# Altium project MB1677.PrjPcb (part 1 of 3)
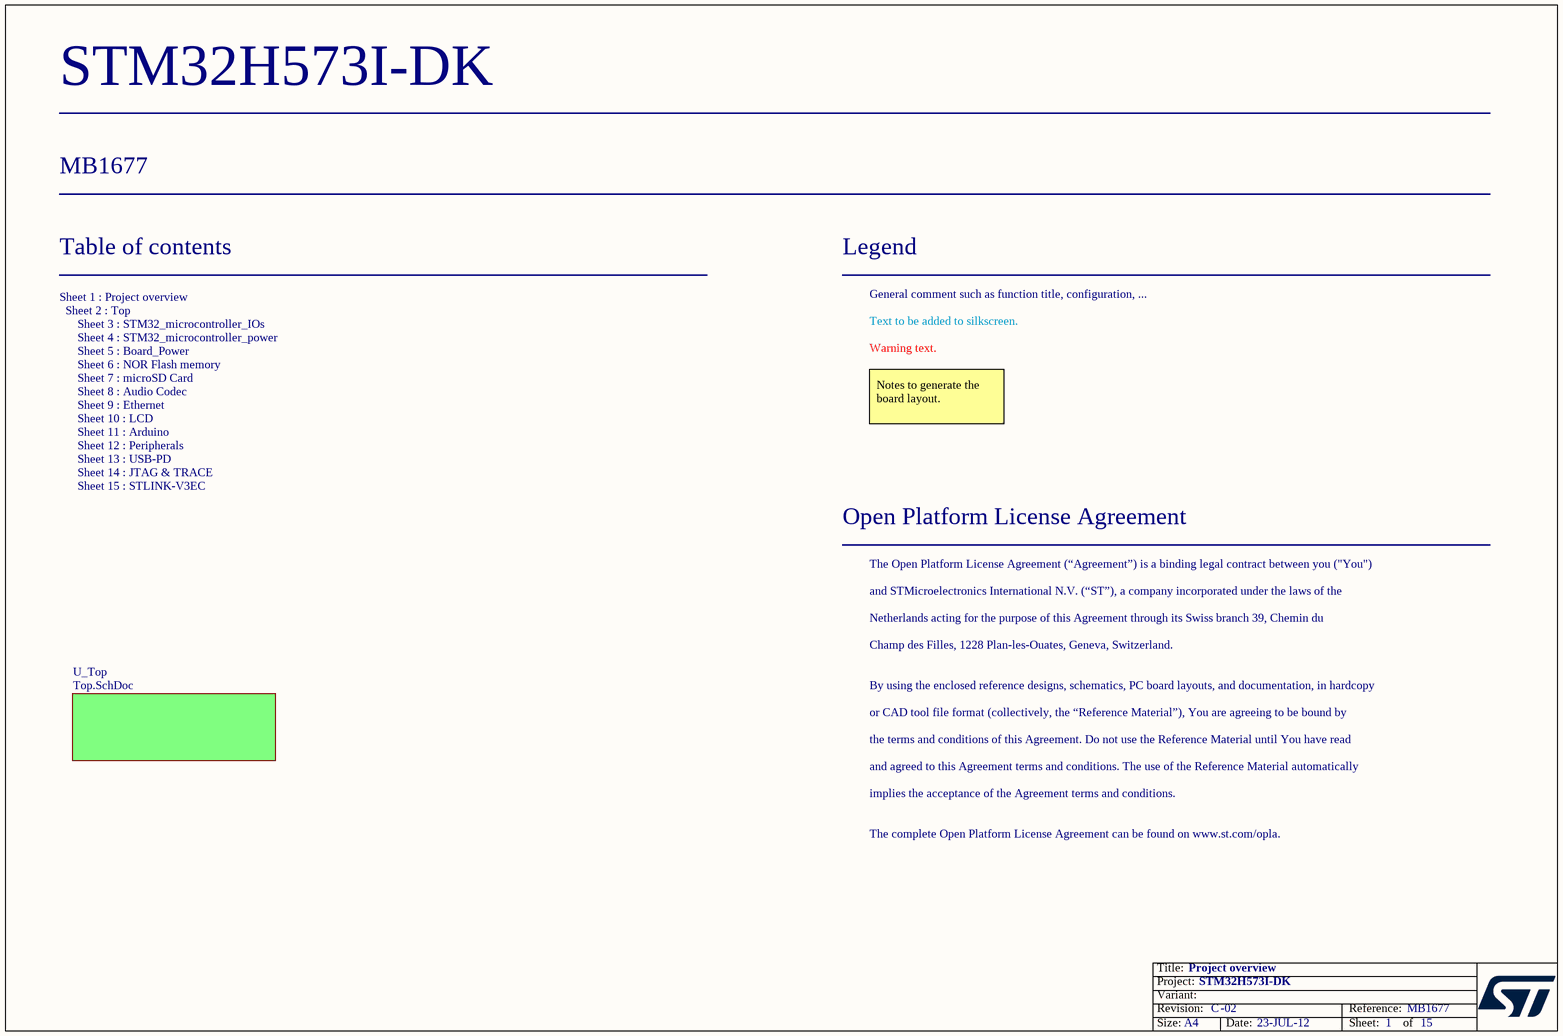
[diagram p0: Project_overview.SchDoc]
Board_Assembly_Revision: 02; Board_Document_Date: 23-JUL-12; Board_Name: STM32H573I-DK; Board_PCB_Revision: C; Board_Reference: MB1677
15 sheets, 390 parts. Net scope: flat (ports and power ports of the same name join across sheets).
Board file: MB1677.PcbDoc
Sheets:
  Project_overview.SchDoc
    U_Top = Top.SchDoc
      U_Audio_Codec = Audio_Codec.SchDoc
      U_LCD = LCD.SchDoc
      U_Peripherals = Peripherals.SchDoc
      U_Arduino = Arduino.SchDoc
      U_JTAG = JTAG.SchDoc
      U_Ethernet = Ethernet.SchDoc
      U_STLINK_V3EC = STLINK_V3EC.SchDoc
      U_Board_power = Board_power.SchDoc
      U_STM32_microcontroller_power = STM32_microcontroller_power.SchDoc
      U_STM32_microcontroller_IOs = STM32_microcontroller_IOs.SchDoc
      U_USB-PD = USB-PD.SchDoc
      U_microSDcard = microSDcard.SchDoc
      U_NOR Flash memory = NOR Flash memory.SchDoc

## Sheet Project_overview.SchDoc: Project overview
size A4; Date: Not used; ApprovedBy: Not used; CheckedBy: Not used; Author: Not used; CompanyName: STMicroelectronics; DrawnBy: Not used; Engineer: Not used; Organization: Not used; Address1: Not used; Address2: Not used; Address3: Not used; Address4: Not used; DocumentNumber: 1; Revision: Not used; SheetNumber: 1; SheetTotal: 15

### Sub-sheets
U_Top = Top.SchDoc: no entries

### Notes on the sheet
- Table of contents
- Legend
- General comment such as function title, configuration, ...
- Text to be added to silkscreen.
- Warning text.
- Notes to generate the board layout.
- Sheet 1 : Project overview
  Sheet 2 : Top
  Sheet 3 : STM32_microcontroller_IOs
  Sheet 4 : STM32_microcontroller_power
  Sheet 5 : Board_Power
  Sheet 6 : NOR Flash memory
  Sheet 7 : microSD Card
  Sheet 8 : Audio Codec
  Sheet 9 : Ethernet
  Sheet 10 : LCD
  Sheet 11 : Arduino
  Sheet 12 : Peripherals
  Sheet 13 : USB-PD
  Sheet 14 : JTAG & TRACE
  Sheet 15 : STLINK-V3EC
- Open Platform License Agreement
- The Open Platform License Agreement (“Agreement”) is a binding legal contract between you ("You")
- and STMicroelectronics International N.V. (“ST”), a company incorporated under the laws of the
- Netherlands acting for the purpose of this Agreement through its Swiss branch 39, Chemin du
- Champ des Filles, 1228 Plan-les-Ouates, Geneva, Switzerland.
- By using the enclosed reference designs, schematics, PC board layouts, and documentation, in hardcopy
- or CAD tool file format (collectively, the “Reference Material”), You are agreeing to be bound by
- the terms and conditions of this Agreement. Do not use the Reference Material until You have read
- and agreed to this Agreement terms and conditions. The use of the Reference Material automatically
- implies the acceptance of the Agreement terms and conditions.
- The complete Open Platform License Agreement can be found on www.st.com/opla.

## Sheet Top.SchDoc: TOP
size A3; Date: Not used; ApprovedBy: Not used; CheckedBy: Not used; Author: Not used; CompanyName: STMicroelectronics; DrawnBy: Not used; Engineer: Not used; Organization: Not used; Address1: Not used; Address2: Not used; Address3: Not used; Address4: Not used; DocumentNumber: 2; Revision: Not used; SheetNumber: 2; SheetTotal: 15
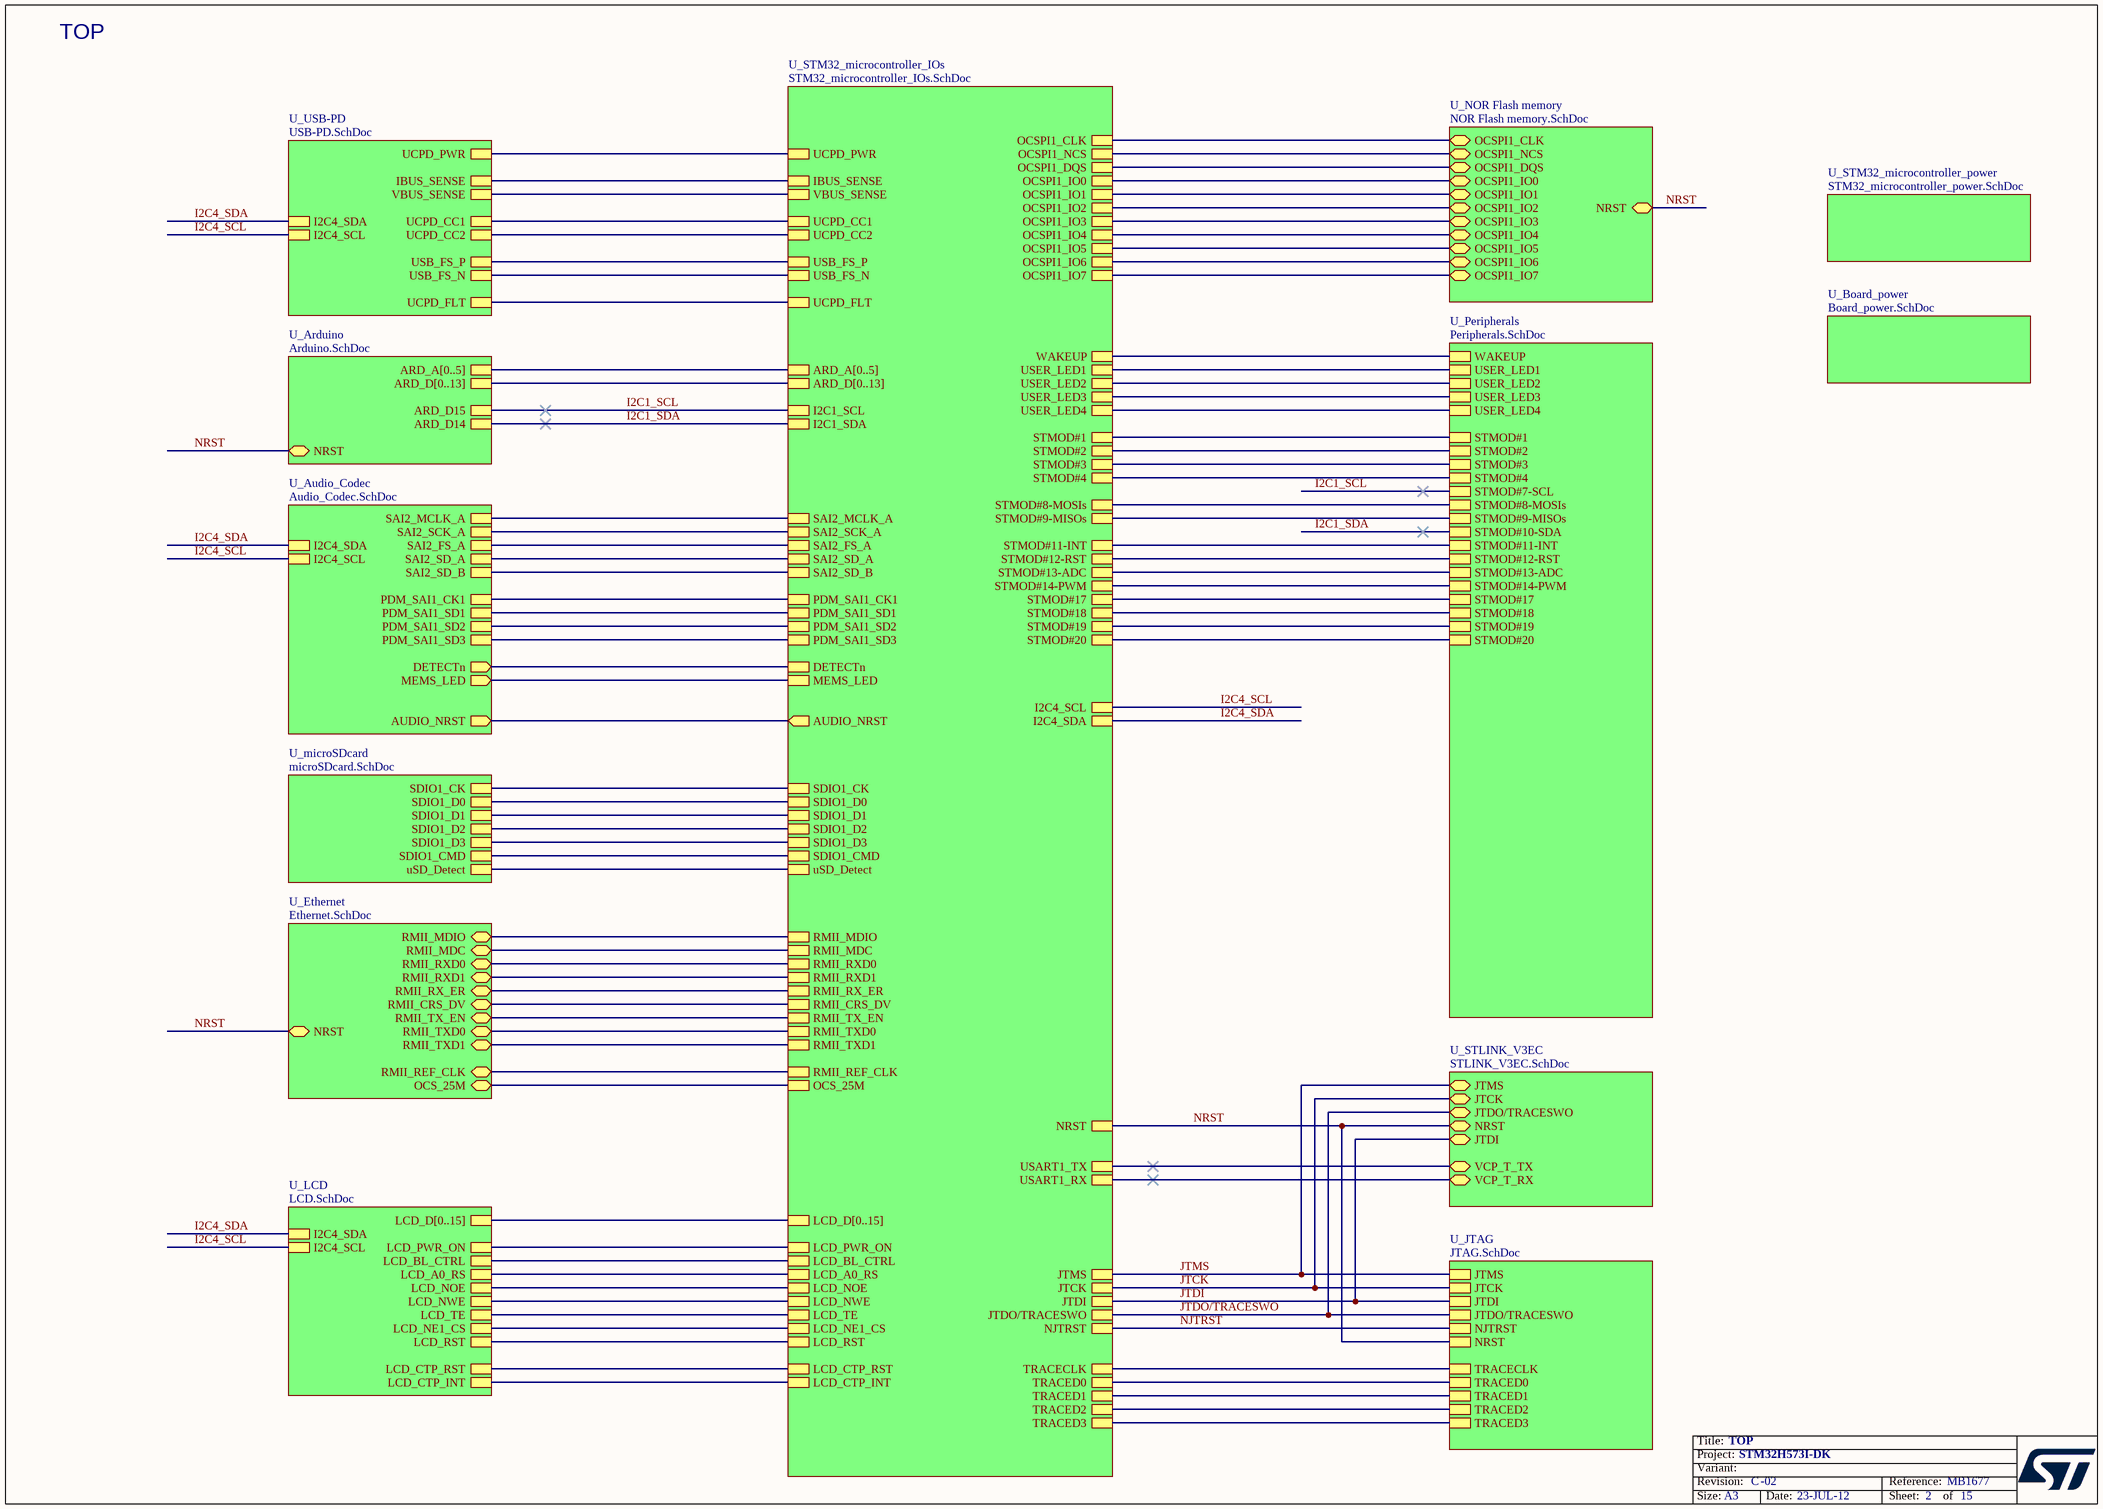
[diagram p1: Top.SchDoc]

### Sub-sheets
U_Arduino = Arduino.SchDoc: ARD_D15, ARD_D14, ARD_A[0..5], NRST (bidir), ARD_D[0..13]
U_Audio_Codec = Audio_Codec.SchDoc: AUDIO_NRST (out), MEMS_LED (out), SAI2_SCK_A, SAI2_MCLK_A, SAI2_SD_B, DETECTn (out), SAI2_FS_A, SAI2_SD_A, I2C4_SCL, I2C4_SDA, PDM_SAI1_CK1, PDM_SAI1_SD2, PDM_SAI1_SD1, PDM_SAI1_SD3
U_Board_power = Board_power.SchDoc: no entries
U_Ethernet = Ethernet.SchDoc: RMII_TXD0 (bidir), RMII_TX_EN (bidir), RMII_RXD0 (bidir), RMII_REF_CLK (bidir), RMII_CRS_DV (bidir), RMII_MDC (bidir), RMII_MDIO (bidir), NRST (bidir), RMII_TXD1 (bidir), RMII_RXD1 (bidir), RMII_RX_ER (bidir), OCS_25M (bidir)
U_JTAG = JTAG.SchDoc: JTMS, JTCK, JTDI, JTDO/TRACESWO, NJTRST, NRST, TRACED0, TRACED1, TRACECLK, TRACED2, TRACED3
U_LCD = LCD.SchDoc: LCD_BL_CTRL, LCD_PWR_ON, LCD_RST, LCD_A0_RS, LCD_CTP_RST, LCD_TE, LCD_NOE, LCD_NE1_CS, LCD_D[0..15], LCD_CTP_INT, LCD_NWE, I2C4_SCL, I2C4_SDA
U_microSDcard = microSDcard.SchDoc: SDIO1_D0, SDIO1_D1, SDIO1_D2, SDIO1_D3, SDIO1_CMD, SDIO1_CK, uSD_Detect
U_NOR Flash memory = NOR Flash memory.SchDoc: NRST (bidir), OCSPI1_IO0 (bidir), OCSPI1_IO1 (bidir), OCSPI1_IO2 (bidir), OCSPI1_IO3 (bidir), OCSPI1_IO4 (bidir), OCSPI1_IO5 (bidir), OCSPI1_IO6 (bidir), OCSPI1_IO7 (bidir), OCSPI1_DQS (bidir), OCSPI1_CLK (bidir), OCSPI1_NCS (bidir)
U_Peripherals = Peripherals.SchDoc: WAKEUP, USER_LED2, USER_LED1, STMOD#2, STMOD#1, STMOD#4, USER_LED3, USER_LED4, STMOD#14-PWM, STMOD#8-MOSIs, STMOD#3, STMOD#13-ADC, STMOD#9-MISOs, STMOD#7-SCL, STMOD#10-SDA, STMOD#11-INT, STMOD#12-RST, STMOD#17, STMOD#18, STMOD#19, STMOD#20
U_STLINK_V3EC = STLINK_V3EC.SchDoc: JTCK (bidir), JTMS (bidir), JTDI (bidir), VCP_T_TX (bidir), VCP_T_RX (bidir), JTDO/TRACESWO (bidir), NRST (bidir)
U_STM32_microcontroller_IOs = STM32_microcontroller_IOs.SchDoc: OCSPI1_NCS, SAI2_MCLK_A, NRST, OCSPI1_DQS, OCSPI1_CLK, LCD_D[0..15], uSD_Detect, RMII_MDIO, SAI2_SD_B, SAI2_FS_A, SAI2_SCK_A, SAI2_SD_A, USER_LED2, JTMS, JTCK, JTDI, JTDO/TRACESWO, NJTRST, OCSPI1_IO1, OCSPI1_IO2, OCSPI1_IO3, OCSPI1_IO4, OCSPI1_IO7, OCSPI1_IO6, OCSPI1_IO5, RMII_CRS_DV, WAKEUP, USER_LED1, RMII_RXD1, UCPD_CC1, STMOD#1, STMOD#2, STMOD#4, STMOD#3, STMOD#9-MISOs, STMOD#8-MOSIs, STMOD#13-ADC, USART1_TX, USART1_RX, STMOD#11-INT, STMOD#12-RST, STMOD#14-PWM, STMOD#18, RMII_REF_CLK, RMII_RXD0, RMII_TXD0, ARD_A[0..5], ARD_D[0..13], RMII_MDC, RMII_TXD1, RMII_TX_EN, SDIO1_D0, SDIO1_D1, SDIO1_D2, SDIO1_D3, SDIO1_CK, SDIO1_CMD, OCSPI1_IO0, LCD_RST, LCD_BL_CTRL, LCD_CTP_RST, LCD_PWR_ON, USER_LED3, USER_LED4, UCPD_CC2, OCS_25M, LCD_CTP_INT, LCD_NE1_CS, LCD_NOE, LCD_NWE, USB_FS_N, USB_FS_P, RMII_RX_ER, LCD_A0_RS, I2C4_SCL, I2C4_SDA, IBUS_SENSE, UCPD_PWR, UCPD_FLT, VBUS_SENSE, DETECTn, MEMS_LED, LCD_TE, I2C1_SCL, I2C1_SDA, AUDIO_NRST (out), PDM_SAI1_SD3, PDM_SAI1_CK1, PDM_SAI1_SD2, PDM_SAI1_SD1, STMOD#19, STMOD#20, STMOD#17, TRACECLK, TRACED0, TRACED1, TRACED2, TRACED3
U_STM32_microcontroller_power = STM32_microcontroller_power.SchDoc: no entries
U_USB-PD = USB-PD.SchDoc: UCPD_PWR, IBUS_SENSE, UCPD_CC1, UCPD_CC2, UCPD_FLT, USB_FS_P, USB_FS_N, VBUS_SENSE, I2C4_SCL, I2C4_SDA

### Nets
I2C1_SCL: sheet U_Peripherals/STMOD#7-SCL, sheet U_Arduino/ARD_D15, sheet U_STM32_microcontroller_IOs/I2C1_SCL
I2C1_SDA: sheet U_Peripherals/STMOD#10-SDA, sheet U_Arduino/ARD_D14, sheet U_STM32_microcontroller_IOs/I2C1_SDA
I2C4_SCL: sheet U_Audio_Codec/I2C4_SCL, sheet U_LCD/I2C4_SCL, sheet U_STM32_microcontroller_IOs/I2C4_SCL, sheet U_USB-PD/I2C4_SCL
I2C4_SDA: sheet U_Audio_Codec/I2C4_SDA, sheet U_LCD/I2C4_SDA, sheet U_STM32_microcontroller_IOs/I2C4_SDA, sheet U_USB-PD/I2C4_SDA
JTCK: sheet U_JTAG/JTCK, sheet U_STLINK_V3EC/JTCK, sheet U_STM32_microcontroller_IOs/JTCK
JTDI: sheet U_JTAG/JTDI, sheet U_STLINK_V3EC/JTDI, sheet U_STM32_microcontroller_IOs/JTDI
JTDO/TRACESWO: sheet U_JTAG/JTDO/TRACESWO, sheet U_STLINK_V3EC/JTDO/TRACESWO, sheet U_STM32_microcontroller_IOs/JTDO/TRACESWO
JTMS: sheet U_JTAG/JTMS, sheet U_STLINK_V3EC/JTMS, sheet U_STM32_microcontroller_IOs/JTMS
NJTRST: sheet U_JTAG/NJTRST, sheet U_STM32_microcontroller_IOs/NJTRST
NRST: sheet U_Arduino/NRST, sheet U_JTAG/NRST, sheet U_Ethernet/NRST, sheet U_STLINK_V3EC/NRST, sheet U_STM32_microcontroller_IOs/NRST, sheet U_NOR Flash memory/NRST
(unnamed): sheet U_Audio_Codec/AUDIO_NRST, sheet U_STM32_microcontroller_IOs/AUDIO_NRST
(unnamed): sheet U_Audio_Codec/MEMS_LED, sheet U_STM32_microcontroller_IOs/MEMS_LED  [a separate net that carries the same name]
(unnamed): sheet U_Audio_Codec/SAI2_SCK_A, sheet U_STM32_microcontroller_IOs/SAI2_SCK_A  [a separate net that carries the same name]
(unnamed): sheet U_Audio_Codec/SAI2_MCLK_A, sheet U_STM32_microcontroller_IOs/SAI2_MCLK_A  [a separate net that carries the same name]
(unnamed): sheet U_Audio_Codec/SAI2_SD_B, sheet U_STM32_microcontroller_IOs/SAI2_SD_B  [a separate net that carries the same name]
(unnamed): sheet U_Audio_Codec/DETECTn, sheet U_STM32_microcontroller_IOs/DETECTn  [a separate net that carries the same name]
(unnamed): sheet U_Audio_Codec/SAI2_FS_A, sheet U_STM32_microcontroller_IOs/SAI2_FS_A  [a separate net that carries the same name]
(unnamed): sheet U_Audio_Codec/SAI2_SD_A, sheet U_STM32_microcontroller_IOs/SAI2_SD_A  [a separate net that carries the same name]
(unnamed): sheet U_Audio_Codec/PDM_SAI1_CK1, sheet U_STM32_microcontroller_IOs/PDM_SAI1_CK1  [a separate net that carries the same name]
(unnamed): sheet U_Audio_Codec/PDM_SAI1_SD2, sheet U_STM32_microcontroller_IOs/PDM_SAI1_SD2  [a separate net that carries the same name]
(unnamed): sheet U_Audio_Codec/PDM_SAI1_SD1, sheet U_STM32_microcontroller_IOs/PDM_SAI1_SD1  [a separate net that carries the same name]
(unnamed): sheet U_Audio_Codec/PDM_SAI1_SD3, sheet U_STM32_microcontroller_IOs/PDM_SAI1_SD3  [a separate net that carries the same name]
(unnamed): sheet U_LCD/LCD_BL_CTRL, sheet U_STM32_microcontroller_IOs/LCD_BL_CTRL  [a separate net that carries the same name]
(unnamed): sheet U_LCD/LCD_PWR_ON, sheet U_STM32_microcontroller_IOs/LCD_PWR_ON  [a separate net that carries the same name]
(unnamed): sheet U_LCD/LCD_RST, sheet U_STM32_microcontroller_IOs/LCD_RST  [a separate net that carries the same name]
(unnamed): sheet U_LCD/LCD_A0_RS, sheet U_STM32_microcontroller_IOs/LCD_A0_RS  [a separate net that carries the same name]
(unnamed): sheet U_LCD/LCD_CTP_RST, sheet U_STM32_microcontroller_IOs/LCD_CTP_RST  [a separate net that carries the same name]
(unnamed): sheet U_LCD/LCD_TE, sheet U_STM32_microcontroller_IOs/LCD_TE  [a separate net that carries the same name]
(unnamed): sheet U_LCD/LCD_NOE, sheet U_STM32_microcontroller_IOs/LCD_NOE  [a separate net that carries the same name]
(unnamed): sheet U_LCD/LCD_NE1_CS, sheet U_STM32_microcontroller_IOs/LCD_NE1_CS  [a separate net that carries the same name]
(unnamed): sheet U_LCD/LCD_CTP_INT, sheet U_STM32_microcontroller_IOs/LCD_CTP_INT  [a separate net that carries the same name]
(unnamed): sheet U_LCD/LCD_NWE, sheet U_STM32_microcontroller_IOs/LCD_NWE  [a separate net that carries the same name]
(unnamed): sheet U_Peripherals/WAKEUP, sheet U_STM32_microcontroller_IOs/WAKEUP  [a separate net that carries the same name]
(unnamed): sheet U_Peripherals/USER_LED2, sheet U_STM32_microcontroller_IOs/USER_LED2  [a separate net that carries the same name]
(unnamed): sheet U_Peripherals/USER_LED1, sheet U_STM32_microcontroller_IOs/USER_LED1  [a separate net that carries the same name]
(unnamed): sheet U_Peripherals/STMOD#2, sheet U_STM32_microcontroller_IOs/STMOD#2  [a separate net that carries the same name]
(unnamed): sheet U_Peripherals/STMOD#1, sheet U_STM32_microcontroller_IOs/STMOD#1  [a separate net that carries the same name]
(unnamed): sheet U_Peripherals/STMOD#4, sheet U_STM32_microcontroller_IOs/STMOD#4  [a separate net that carries the same name]
(unnamed): sheet U_Peripherals/USER_LED3, sheet U_STM32_microcontroller_IOs/USER_LED3  [a separate net that carries the same name]
(unnamed): sheet U_Peripherals/USER_LED4, sheet U_STM32_microcontroller_IOs/USER_LED4  [a separate net that carries the same name]
(unnamed): sheet U_Peripherals/STMOD#14-PWM, sheet U_STM32_microcontroller_IOs/STMOD#14-PWM  [a separate net that carries the same name]
(unnamed): sheet U_Peripherals/STMOD#8-MOSIs, sheet U_STM32_microcontroller_IOs/STMOD#8-MOSIs  [a separate net that carries the same name]
(unnamed): sheet U_Peripherals/STMOD#3, sheet U_STM32_microcontroller_IOs/STMOD#3  [a separate net that carries the same name]
(unnamed): sheet U_Peripherals/STMOD#13-ADC, sheet U_STM32_microcontroller_IOs/STMOD#13-ADC  [a separate net that carries the same name]
(unnamed): sheet U_Peripherals/STMOD#9-MISOs, sheet U_STM32_microcontroller_IOs/STMOD#9-MISOs  [a separate net that carries the same name]
(unnamed): sheet U_Peripherals/STMOD#11-INT, sheet U_STM32_microcontroller_IOs/STMOD#11-INT  [a separate net that carries the same name]
(unnamed): sheet U_Peripherals/STMOD#12-RST, sheet U_STM32_microcontroller_IOs/STMOD#12-RST  [a separate net that carries the same name]
(unnamed): sheet U_Peripherals/STMOD#17, sheet U_STM32_microcontroller_IOs/STMOD#17  [a separate net that carries the same name]
(unnamed): sheet U_Peripherals/STMOD#18, sheet U_STM32_microcontroller_IOs/STMOD#18  [a separate net that carries the same name]
(unnamed): sheet U_Peripherals/STMOD#19, sheet U_STM32_microcontroller_IOs/STMOD#19  [a separate net that carries the same name]
(unnamed): sheet U_Peripherals/STMOD#20, sheet U_STM32_microcontroller_IOs/STMOD#20  [a separate net that carries the same name]
(unnamed): sheet U_JTAG/TRACED0, sheet U_STM32_microcontroller_IOs/TRACED0  [a separate net that carries the same name]
(unnamed): sheet U_JTAG/TRACED1, sheet U_STM32_microcontroller_IOs/TRACED1  [a separate net that carries the same name]
(unnamed): sheet U_JTAG/TRACECLK, sheet U_STM32_microcontroller_IOs/TRACECLK  [a separate net that carries the same name]
(unnamed): sheet U_JTAG/TRACED2, sheet U_STM32_microcontroller_IOs/TRACED2  [a separate net that carries the same name]
(unnamed): sheet U_JTAG/TRACED3, sheet U_STM32_microcontroller_IOs/TRACED3  [a separate net that carries the same name]
(unnamed): sheet U_Ethernet/RMII_TXD0, sheet U_STM32_microcontroller_IOs/RMII_TXD0  [a separate net that carries the same name]
(unnamed): sheet U_Ethernet/RMII_TX_EN, sheet U_STM32_microcontroller_IOs/RMII_TX_EN  [a separate net that carries the same name]
(unnamed): sheet U_Ethernet/RMII_RXD0, sheet U_STM32_microcontroller_IOs/RMII_RXD0  [a separate net that carries the same name]
(unnamed): sheet U_Ethernet/RMII_REF_CLK, sheet U_STM32_microcontroller_IOs/RMII_REF_CLK  [a separate net that carries the same name]
(unnamed): sheet U_Ethernet/RMII_CRS_DV, sheet U_STM32_microcontroller_IOs/RMII_CRS_DV  [a separate net that carries the same name]
(unnamed): sheet U_Ethernet/RMII_MDC, sheet U_STM32_microcontroller_IOs/RMII_MDC  [a separate net that carries the same name]
(unnamed): sheet U_Ethernet/RMII_MDIO, sheet U_STM32_microcontroller_IOs/RMII_MDIO  [a separate net that carries the same name]
(unnamed): sheet U_Ethernet/RMII_TXD1, sheet U_STM32_microcontroller_IOs/RMII_TXD1  [a separate net that carries the same name]
(unnamed): sheet U_Ethernet/RMII_RXD1, sheet U_STM32_microcontroller_IOs/RMII_RXD1  [a separate net that carries the same name]
(unnamed): sheet U_Ethernet/RMII_RX_ER, sheet U_STM32_microcontroller_IOs/RMII_RX_ER  [a separate net that carries the same name]
(unnamed): sheet U_Ethernet/OCS_25M, sheet U_STM32_microcontroller_IOs/OCS_25M  [a separate net that carries the same name]
(unnamed): sheet U_STLINK_V3EC/VCP_T_TX, sheet U_STM32_microcontroller_IOs/USART1_TX  [a separate net that carries the same name]
(unnamed): sheet U_STLINK_V3EC/VCP_T_RX, sheet U_STM32_microcontroller_IOs/USART1_RX  [a separate net that carries the same name]
(unnamed): sheet U_STM32_microcontroller_IOs/OCSPI1_NCS, sheet U_NOR Flash memory/OCSPI1_NCS  [a separate net that carries the same name]
(unnamed): sheet U_STM32_microcontroller_IOs/OCSPI1_DQS, sheet U_NOR Flash memory/OCSPI1_DQS  [a separate net that carries the same name]
(unnamed): sheet U_STM32_microcontroller_IOs/OCSPI1_CLK, sheet U_NOR Flash memory/OCSPI1_CLK  [a separate net that carries the same name]
(unnamed): sheet U_STM32_microcontroller_IOs/uSD_Detect, sheet U_microSDcard/uSD_Detect  [a separate net that carries the same name]
(unnamed): sheet U_STM32_microcontroller_IOs/OCSPI1_IO1, sheet U_NOR Flash memory/OCSPI1_IO1  [a separate net that carries the same name]
(unnamed): sheet U_STM32_microcontroller_IOs/OCSPI1_IO2, sheet U_NOR Flash memory/OCSPI1_IO2  [a separate net that carries the same name]
(unnamed): sheet U_STM32_microcontroller_IOs/OCSPI1_IO3, sheet U_NOR Flash memory/OCSPI1_IO3  [a separate net that carries the same name]
(unnamed): sheet U_STM32_microcontroller_IOs/OCSPI1_IO4, sheet U_NOR Flash memory/OCSPI1_IO4  [a separate net that carries the same name]
(unnamed): sheet U_STM32_microcontroller_IOs/OCSPI1_IO7, sheet U_NOR Flash memory/OCSPI1_IO7  [a separate net that carries the same name]
(unnamed): sheet U_STM32_microcontroller_IOs/OCSPI1_IO6, sheet U_NOR Flash memory/OCSPI1_IO6  [a separate net that carries the same name]
(unnamed): sheet U_STM32_microcontroller_IOs/OCSPI1_IO5, sheet U_NOR Flash memory/OCSPI1_IO5  [a separate net that carries the same name]
(unnamed): sheet U_STM32_microcontroller_IOs/UCPD_CC1, sheet U_USB-PD/UCPD_CC1  [a separate net that carries the same name]
(unnamed): sheet U_STM32_microcontroller_IOs/SDIO1_D0, sheet U_microSDcard/SDIO1_D0  [a separate net that carries the same name]
(unnamed): sheet U_STM32_microcontroller_IOs/SDIO1_D1, sheet U_microSDcard/SDIO1_D1  [a separate net that carries the same name]
(unnamed): sheet U_STM32_microcontroller_IOs/SDIO1_D2, sheet U_microSDcard/SDIO1_D2  [a separate net that carries the same name]
(unnamed): sheet U_STM32_microcontroller_IOs/SDIO1_D3, sheet U_microSDcard/SDIO1_D3  [a separate net that carries the same name]
(unnamed): sheet U_STM32_microcontroller_IOs/SDIO1_CK, sheet U_microSDcard/SDIO1_CK  [a separate net that carries the same name]
(unnamed): sheet U_STM32_microcontroller_IOs/SDIO1_CMD, sheet U_microSDcard/SDIO1_CMD  [a separate net that carries the same name]
(unnamed): sheet U_STM32_microcontroller_IOs/OCSPI1_IO0, sheet U_NOR Flash memory/OCSPI1_IO0  [a separate net that carries the same name]
(unnamed): sheet U_STM32_microcontroller_IOs/UCPD_CC2, sheet U_USB-PD/UCPD_CC2  [a separate net that carries the same name]
(unnamed): sheet U_STM32_microcontroller_IOs/USB_FS_N, sheet U_USB-PD/USB_FS_N  [a separate net that carries the same name]
(unnamed): sheet U_STM32_microcontroller_IOs/USB_FS_P, sheet U_USB-PD/USB_FS_P  [a separate net that carries the same name]
(unnamed): sheet U_STM32_microcontroller_IOs/IBUS_SENSE, sheet U_USB-PD/IBUS_SENSE  [a separate net that carries the same name]
(unnamed): sheet U_STM32_microcontroller_IOs/UCPD_PWR, sheet U_USB-PD/UCPD_PWR  [a separate net that carries the same name]
(unnamed): sheet U_STM32_microcontroller_IOs/UCPD_FLT, sheet U_USB-PD/UCPD_FLT  [a separate net that carries the same name]
(unnamed): sheet U_STM32_microcontroller_IOs/VBUS_SENSE, sheet U_USB-PD/VBUS_SENSE  [a separate net that carries the same name]

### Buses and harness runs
bus sheet U_Arduino/ARD_A[0..5] = sheet U_STM32_microcontroller_IOs/ARD_A[0..5]
bus sheet U_Arduino/ARD_D[0..13] = sheet U_STM32_microcontroller_IOs/ARD_D[0..13]
bus sheet U_LCD/LCD_D[0..15] = sheet U_STM32_microcontroller_IOs/LCD_D[0..15]

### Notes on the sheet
- TOP

## Sheet Audio_Codec.SchDoc: Audio Codec
size A4; Date: Not used; ApprovedBy: Not used; CheckedBy: Not used; Author: Not used; CompanyName: STMicroelectronics; DrawnBy: Not used; Engineer: Not used; Organization: Not used; Address1: Not used; Address2: Not used; Address3: Not used; Address4: Not used; DocumentNumber: 8; Revision: Not used; SheetNumber: 8; SheetTotal: 15
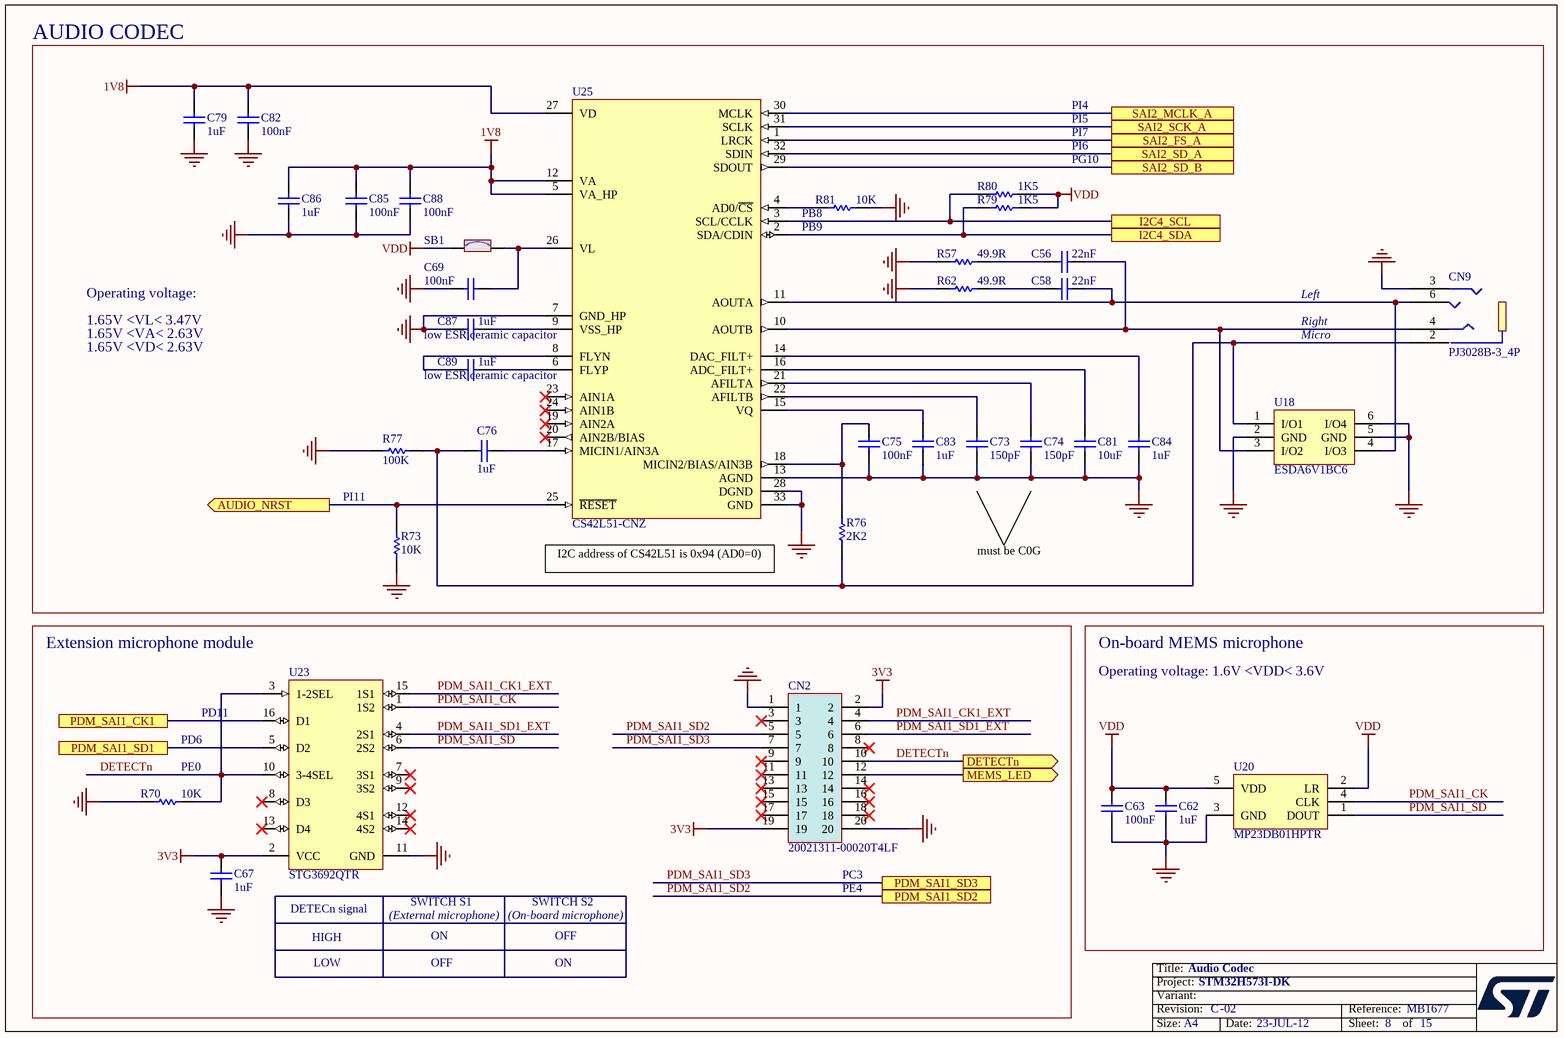
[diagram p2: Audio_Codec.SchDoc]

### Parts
C56  value 22nF  [C0603]  (hidden comment: Capacitor)
C58  value 22nF  [C0603]  (hidden comment: Capacitor)
C62  value 1uF  [C0402]  (hidden comment: Capacitor)
C63  value 100nF  [C0402]  (hidden comment: Capacitor)
C67  value 1uF  [C0402]  (hidden comment: Capacitor)
C69  value 100nF  [C0402]  (hidden comment: Capacitor)
C73  value 150pF  [C0402]  (hidden comment: Capacitor)
C74  value 150pF  [C0402]  (hidden comment: Capacitor)
C75  value 100nF  [C0402]  (hidden comment: Capacitor)
C76  value 1uF  [C0402]  (hidden comment: Capacitor)
C79  value 1uF  [C0402]  (hidden comment: Capacitor)
C81  value 10uF  [C0603]  (hidden comment: Capacitor)
C82  value 100nF  [C0402]  (hidden comment: Capacitor)
C83  value 1uF  [C0402]  (hidden comment: Capacitor)
C84  value 1uF  [C0402]  (hidden comment: Capacitor)
C85  value 100nF  [C0402]  (hidden comment: Capacitor)
C86  value 1uF  [C0402]  (hidden comment: Capacitor)
C87  value 1uF  [C0402]  (hidden comment: Capacitor)
C88  value 100nF  [C0402]  (hidden comment: Capacitor)
C89  value 1uF  [C0402]  (hidden comment: Capacitor)
CN2  value 20021311-00020T4LF  [CON_FCI_20021311-XXX20XXLF]  (hidden comment: Socket 10x2)
CN9  value PJ3028B-3_4P  [CON_PHONE-JACK-3P5_HY_PJ3028B]  (hidden comment: Jack_PJ3028B-3_4P)
R57  value 49.9R  [R0603]  (hidden comment: Resistor)
R62  value 49.9R  [R0603]  (hidden comment: Resistor)
R70  value 10K  [R0402]  (hidden comment: Resistor)
R73  value 10K  [R0402]  (hidden comment: Resistor)
R76  value 2K2  [R0402]  (hidden comment: Resistor)
R77  value 100K  [R0402]  (hidden comment: Resistor)
R79  value 1K5  [R0402]  (hidden comment: Resistor)
R80  value 1K5  [R0402]  (hidden comment: Resistor)
R81  value 10K  [R0402]  (hidden comment: Resistor)
SB1  SB_ON  [SOLDER-BRIDGE_R0603-0R]  (value not drawn)
U18  ESDA6V1BC6  [ESD_SOT23-6L]
U20  value MP23DB01HPTR  [MIC_STM_MP23DB01MMTR]  (hidden comment: MP23DB01MMTR)
U23  STG3692QTR  [ICC_UFQFN16-EPAD_2P6X1P8_P040]
U25  CS42L51-CNZ  [ICC_QFN32-EPAD_5X5_P050]

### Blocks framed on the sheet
AUDIO CODEC: C56 C58 C69 C73-C76 C79 C81-C89 CN9 R57 R62 R73 R76 R77 R79-R81 SB1 U18 U25
Extension microphone module: C67 CN2 R70 U23
On-board MEMS microphone: C62 C63 U20

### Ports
AUDIO_NRST (out), DETECTn (out), I2C4_SCL, I2C4_SDA, MEMS_LED (out), PDM_SAI1_CK1, PDM_SAI1_SD1, PDM_SAI1_SD2, PDM_SAI1_SD3, SAI2_FS_A, SAI2_MCLK_A, SAI2_SCK_A, SAI2_SD_A, SAI2_SD_B

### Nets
1V8: C79.2 C82.2 C85.2 C86.2 C88.2 U25.5(VA_HP) U25.12(VA) U25.27(VD)
3V3: C67.2 CN2.2 CN2.19 U23.2(VCC)
GND: C62.2 C63.1 C67.1 C69.2 C73.1 C74.1 C75.2 C79.1 C81.1 C82.1 C83.1 C84.1 C85.1 C86.1 C87.1 C88.1 CN2.1 CN2.20 CN9.3 R57.2 R62.2 R70.1 R73.2 R77.2 R81.2 U18.2(GND) U18.5(GND) U18.6(I/O4) U20.3(GND) U23.11(GND) U25.7(GND_HP) U25.13(AGND) U25.28(DGND) U25.33(GND)
VDD: C62.1 C63.2 R79.2 R80.2 SB1.1 U20.2(LR) U20.5(VDD)
AUDIO_NRST: R73.1 U25.25(~{RESET}) ; port AUDIO_NRST
DETECTn: CN2.10 R70.2 U23.3(1-2SEL) U23.10(3-4SEL) ; port DETECTn
I2C4_SCL: R80.1 U25.3(SCL/CCLK) ; port I2C4_SCL
I2C4_SDA: R79.1 U25.2(SDA/CDIN) ; port I2C4_SDA
MEMS_LED: CN2.12 ; port MEMS_LED
PDM_SAI1_CK: U20.4(CLK) U23.1(1S2)
PDM_SAI1_CK1: U23.16(D1) ; port PDM_SAI1_CK1
PDM_SAI1_CK1_EXT: CN2.4 U23.15(1S1)
PDM_SAI1_SD: U20.1(DOUT) U23.6(2S2)
PDM_SAI1_SD1: U23.5(D2) ; port PDM_SAI1_SD1
PDM_SAI1_SD1_EXT: CN2.6 U23.4(2S1)
PDM_SAI1_SD2: CN2.5 ; port PDM_SAI1_SD2
PDM_SAI1_SD3: CN2.7 ; port PDM_SAI1_SD3
SAI2_FS_A: U25.1(LRCK) ; port SAI2_FS_A
SAI2_MCLK_A: U25.30(MCLK) ; port SAI2_MCLK_A
SAI2_SCK_A: U25.31(SCLK) ; port SAI2_SCK_A
SAI2_SD_A: U25.32(SDIN) ; port SAI2_SD_A
SAI2_SD_B: U25.29(SDOUT) ; port SAI2_SD_B
NetC56_1: C56.1 R57.1
NetC56_2: C56.2 CN9.4 U18.3(I/O2) U25.10(AOUTB)
NetC58_1: C58.1 R62.1
NetC58_2: C58.2 CN9.6 U18.4(I/O3) U25.11(AOUTA)
NetC69_1: C69.1 SB1.2 U25.26(VL)
NetC73_2: C73.2 U25.22(AFILTB)
NetC74_2: C74.2 U25.21(AFILTA)
NetC75_1: C75.1 R76.2 U25.18(MICIN2/BIAS/AIN3B)
NetC76_1: C76.1 CN9.2 R76.1 R77.1 U18.1(I/O1)
NetC76_2: C76.2 U25.17(MICIN1/AIN3A)
NetC81_2: C81.2 U25.16(ADC_FILT+)
NetC83_2: C83.2 U25.15(VQ)
NetC84_2: C84.2 U25.14(DAC_FILT+)
NetC87_2: C87.2 U25.9(VSS_HP)
NetC89_1: C89.1 U25.8(FLYN)
NetC89_2: C89.2 U25.6(FLYP)
NetR81_1: R81.1 U25.4(AD0/~{CS})

Not connected (* = marked no-connect by the designer): CN2 3* 8* 9* 11* 13* 14* 15* 16* 17* 18*; U23 7(3S1)* 8(D3)* 9(3S2)* 12(4S1)* 13(D4)* 14(4S2)*; U25 19(AIN2A)* 20(AIN2B/BIAS)* 23(AIN1A)* 24(AIN1B)*

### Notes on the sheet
- PI4
- PI5
- PI7
- PI6
- PG10
- (near R81) PB8
- (near R81) PB9
- Operating voltage:
- Left
- 1.65V <VL< 3.47V
- 1.65V <VA< 2.63V
- 1.65V <VD< 2.63V
- low ESR ceramic capacitor
- Right
- Micro
- PI11
- (near U25) I2C address of CS42L51 is 0x94 (AD0=0)
- must be C0G
- PD11
- Operating voltage: 1.6V <VDD< 3.6V
- PD6
- (near R70) PE0
- DETECn signal
- (External microphone)
- (near U23) SWITCH S1
- (On-board microphone)
- SWITCH S2
- PE4
- (near CN2) PC3
- HIGH
- LOW
- OFF
- ON

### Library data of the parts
C56 C58 = MCD-00555: Capacitor, MLCC, 22nF, 10%, 25V, X7R, 0603, T=0,8mm; Manufacturer_Part_Number: CC0603KRX7R8BB223; Manufacturer: YAGEO; Provided_By: SUBCO
C62 C79 C83 C84 C86 C87 C89 = MCD-01722: Capacitor, 1uF, 10V, X5R, 10%, 0402, T=0.5mm; Manufacturer_Part_Number: CC0402KRX5R6BB105; Manufacturer: YAGEO; Provided_By: SUBCO
C63 = MCD-00102: Capacitor, MLCC, 100nF, 16V, X7R, +/-10%, 0402, T=0,5mm; Part_Preference: Not recommended; Manufacturer: YAGEO; Manufacturer_Part_Number: CC0402KRX7R7BB104; Alternate_Manufacturer: MURATA; Alternate_Manufacturer_Part_Number: GCM155R71C104KA55D; Order_Code_RS: 616-9701
C67 C76 = MCD-00095: Capacitor, MLCC, 1uF, 25V, X5R, +/-10%, 0402, T=0,5mm; Part_Preference: Recommended; Manufacturer: MURATA; Manufacturer_Part_Number: GRM155R61E105KA12; Alternate_Manufacturer_Part_Number: GRM155R60J105KE19; Order_Code_RS: 846-7287
C69 C75 C82 C85 C88 = MCD-00102: Capacitor, MLCC, 100nF, 16V, X7R, 10%, 0402, T=0,5mm; Manufacturer_Part_Number: CC0402KRX7R7BB104; Manufacturer: YAGEO; Alternate_Manufacturer_Part_Number: GCM155R71C104KA55D; Alternate_Manufacturer: MURATA; Provided_By: SUBCO
C73 C74 = MCD-00672: Capacitor, MLCC, 150pF, 50V, NPO, 5%, 0402, T=0,5mm; Manufacturer_Part_Number: CC0402JRNPO9BN151; Manufacturer: YAGEO; Provided_By: SUBCO
C81 = MCD-00098: Capacitor, MLCC, 10uF, 6V3, X5R, 10%, 0603, T=0,8mm; Manufacturer_Part_Number: CC0603KRX5R5BB106; Manufacturer: YAGEO; Provided_By: SUBCO
CN2 = MCD-00147: Socket for MB1299, 10x2, 1.27mm, VR, TH, Height 4.30mm/2.40mm; Part_Preference: Recommended; Part_Type: Connector; Manufacturer: AMPHENOL ICC (FCI); Alternate_Manufacturer: JIUBABA; Alternate_Manufacturer_Part_Number: 234220S1410
CN9 = MCD-00263: Connector Jack Socket Stereo 3.5mm, 4 pins, RA, SMT, Black; Part_Preference: Recommended; Manufacturer: QIAOD
R57 R62 = MCD-00564: Resistor,49R9,0603,1%,1/10W; Manufacturer_Part_Number: RC0603FR-0749R9L; Manufacturer: YAGEO; Provided_By: SUBCO
R70 = MCD-00053: Resistor,10K,0402,1%,1/16W; BMS_Part_Number: 9131590; Part_Preference: Recommended; Manufacturer: YAGEO; Manufacturer_Part_Number: RC0402FR-0710KL
R73 R81 = MCD-00053: Resistor,10K,0402,1%,1/16W; Manufacturer_Part_Number: RC0402FR-0710KL; Manufacturer: YAGEO; Provided_By: SUBCO
R76 = MCD-00057: Resistor,2K2,0402,1%,1/16W; Part_Preference: Recommended; Manufacturer: YAGEO; Manufacturer_Part_Number: RC0402FR-072K2L
R77 = MCD-00059: Resistor,100K,0402,1%,1/16W; Manufacturer_Part_Number: RC0402FR-07100KL; Manufacturer: YAGEO; Alternate_Manufacturer_Part_Number: RT0402FRE07100KL; Provided_By: SUBCO
R79 R80 = MCD-00068: Resistor,1K5,0402,1%,1/16W; Manufacturer_Part_Number: RC0402FR-071K5L; Manufacturer: YAGEO; Provided_By: SUBCO
SB1 = MCD-00071: Solder Bridge ON; Part_Type: Mechanical; Manufacturer_Part_Number: RC0603JR-070RL; Manufacturer: YAGEO; Provided_By: SUBCO
U18 = MCD-00247: Quad Bidir ESD protection; BMS_Part_Number: 9179038; Part_Preference: Recommended; Part_Type: Diode; Manufacturer: STMICROELECTRONICS; Manufacturer_HQ_COO: EU
U20 = MCD-02122: MEMS sensors , omnidirectionnal digital microphone; Part_Type: IC; Part_Preference: Recommended; Manufacturer: STMICROELECTRONICS; Manufacturer_HQ_COO: EU; Component_Country_Of_Origin: China; ShowFields: YES; ID: 4222
U23 = MCD-00317: Low voltage high bandwidth quad SPDT switch; BMS_Part_Number: 9159018; Part_Preference: Recommended; Part_Type: IC; Manufacturer: STMICROELECTRONICS
U25 = MCD-00265: Low-Power, Stereo Codec with Headphone Amp; Part_Type: IC; Manufacturer: CIRRUS LOGIC; Provided_By: SUBCO

## Sheet LCD.SchDoc: LCD
size A4; Date: Not used; ApprovedBy: Not used; CheckedBy: Not used; Author: Not used; CompanyName: STMicroelectronics; DrawnBy: Not used; Engineer: Not used; Organization: Not used; Address1: Not used; Address2: Not used; Address3: Not used; Address4: Not used; DocumentNumber: 10; Revision: Not used; SheetNumber: 10; SheetTotal: 15
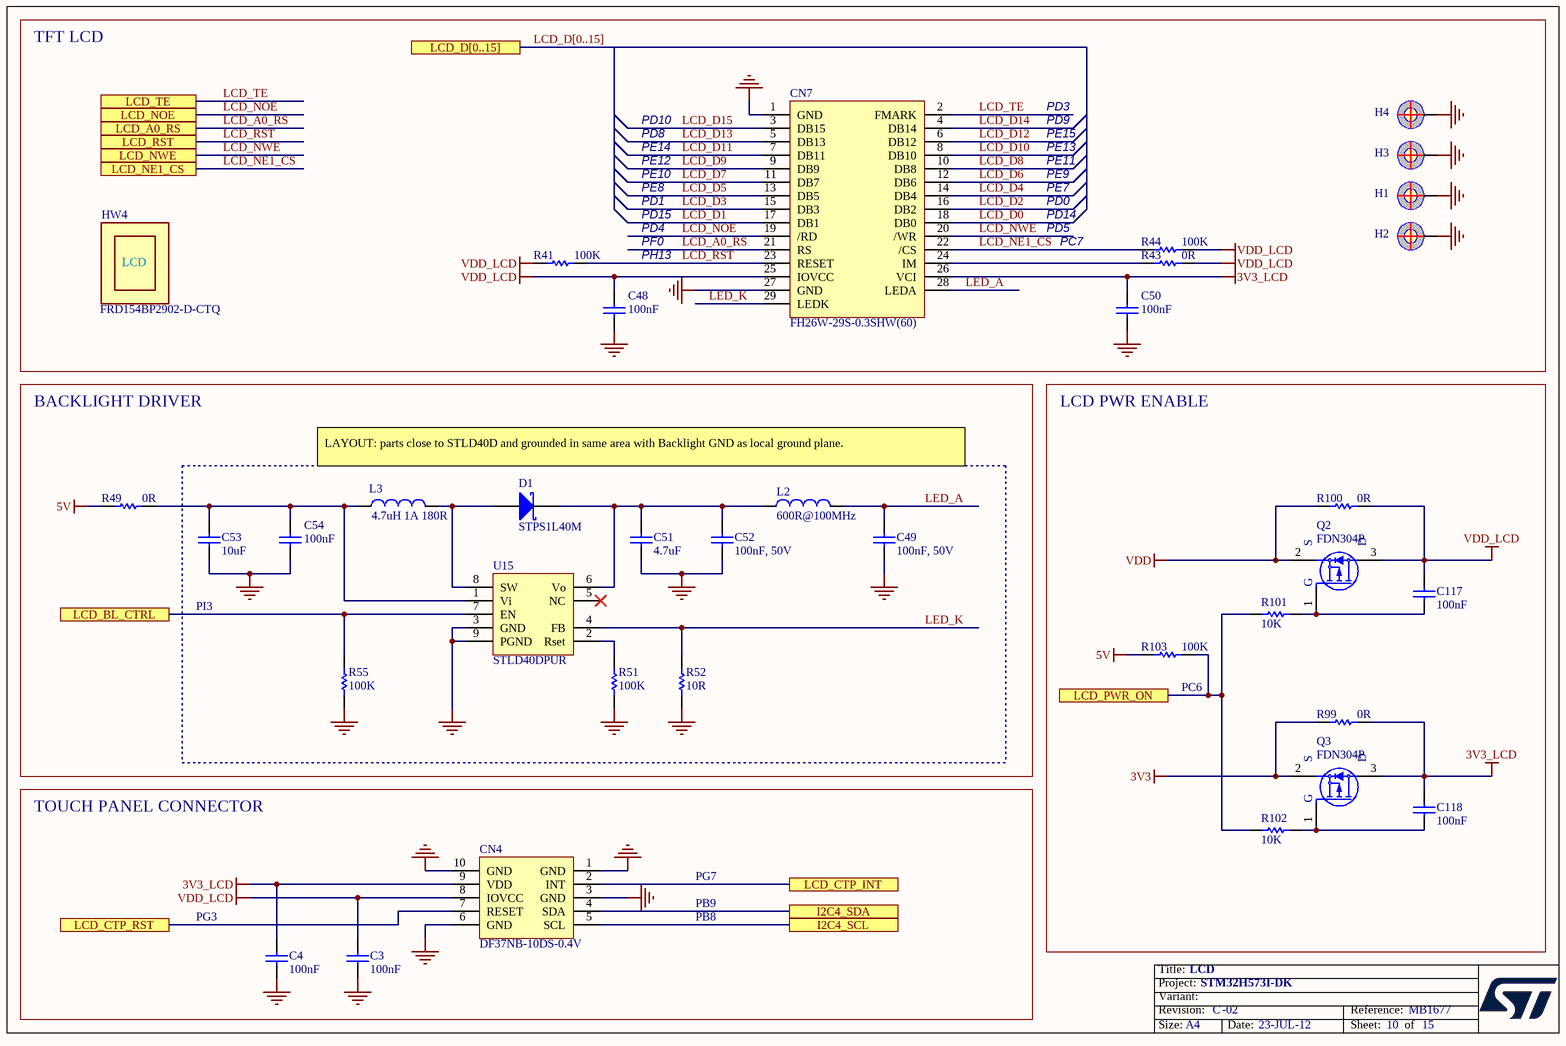
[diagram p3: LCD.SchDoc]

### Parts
C3  value 100nF  [C0402]  (hidden comment: Capacitor)
C4  value 100nF  [C0402]  (hidden comment: Capacitor)
C48  value 100nF  [C0402]  (hidden comment: Capacitor)
C49  value 100nF, 50V  [C0603]  (hidden comment: Capacitor)
C50  value 100nF  [C0402]  (hidden comment: Capacitor)
C51  value 4.7uF  [C1206_H1P25]  (hidden comment: Capacitor)
C52  value 100nF, 50V  [C0603]  (hidden comment: Capacitor)
C53  value 10uF  [C0603]  (hidden comment: Capacitor)
C54  value 100nF  [C0402]  (hidden comment: Capacitor)
C117  value 100nF  [C0402]  (hidden comment: Capacitor)
C118  value 100nF  [C0402]  (hidden comment: Capacitor)
CN4  DF37NB-10DS-0.4V  [CON_HRS_DF37NB-10DS-04V]
CN7  value FH26W-29S-0.3SHW(60)  [CON_HRS_FH26-29S-03SHW]  (hidden comment: FH26-29S-0.3SHW)
D1  STPS1L40M  [DIO_DO216-AA]
H1  POSITION HOLE  [PTH_M1261-3005-N_3P5X6_M3_H14]  (value not drawn)  (no BOM)
H2  POSITION HOLE  [PTH_M1261-3005-N_3P5X6_M3_H14]  (value not drawn)  (no BOM)
H3  POSITION HOLE  [PTH_M1261-3005-N_3P5X6_M3_H14]  (value not drawn)  (no BOM)
H4  POSITION HOLE  [PTH_M1261-3005-N_3P5X6_M3_H14]  (value not drawn)  (no BOM)
HW4  value FRD154BP2902-D-CTQ  [LCD_DRAWING_FRIDA_FRD154BP2902-D-CTQ]  (hidden comment: LCD_MODULE)  (mechanical)
L2  value 600R@100MHz  [L0603]  (hidden comment: BEAD)
L3  value 4.7uH 1A 180R  [L1210_LQH]  (hidden comment: Inductor)
Q2  value FDN304P  [MOS_SOT23]  (hidden comment: MOSFET_FDN304P)
Q3  value FDN304P  [MOS_SOT23]  (hidden comment: MOSFET_FDN304P)
R41  value 100K  [R0402]  (hidden comment: Resistor)
R43  value 0R  [R0402]  (hidden comment: Resistor)
R44  value 100K  [R0402]  (hidden comment: Resistor)
R49  value 0R  [R0402]  (hidden comment: Resistor)
R51  value 100K  [R0402]  (hidden comment: Resistor)
R52  value 10R  [R0402]  (hidden comment: Resistor)
R55  value 100K  [R0402]  (hidden comment: Resistor)
R99  value 0R  [R0402]  (hidden comment: Resistor)
R100  value 0R  [R0402]  (hidden comment: Resistor)
R101  value 10K  [R0402]  (hidden comment: Resistor)
R102  value 10K  [R0402]  (hidden comment: Resistor)
R103  value 100K  [R0402]  (hidden comment: Resistor)
U15  STLD40DPUR  [ICC_QFN8-EPAD_3X3_P065]

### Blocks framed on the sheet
TFT LCD: C48 C50 CN7 H1-H4 HW4 R41 R43 R44
BACKLIGHT DRIVER: R49
LCD PWR ENABLE: C117 C118 Q2 Q3 R99-R103
PI3: C49 C51-C54 D1 L2 L3 R51 R52 R55 U15
TOUCH PANEL CONNECTOR: C3 C4 CN4

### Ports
I2C4_SCL, I2C4_SDA, LCD_A0_RS, LCD_BL_CTRL, LCD_CTP_INT, LCD_CTP_RST, LCD_D[0..15], LCD_NE1_CS, LCD_NOE, LCD_NWE, LCD_PWR_ON, LCD_RST, LCD_TE

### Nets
3V3: Q3.2(S) R99.1
3V3_LCD: C4.2 C50.1 C118.2 CN4.9(VDD) CN7.26(VCI) Q3.3(D) R99.2
5V: R49.1 R103.1
GND: C3.1 C4.1 C48.2 C49.1 C50.2 C51.1 C52.1 C53.1 C54.2 CN4.1(GND) CN4.3(GND) CN4.6(GND) CN4.10(GND) CN7.1(GND) CN7.27(GND) H1.1 H2.1 H3.1 H4.1 R51.1 R52.1 R55.1 U15.3(GND) U15.9(PGND)
VDD: Q2.2(S) R100.1
VDD_LCD: C3.2 C48.1 C117.2 CN4.8(IOVCC) CN7.25(IOVCC) Q2.3(D) R41.1 R43.2 R44.2 R100.2
I2C4_SCL: CN4.5(SCL) ; port I2C4_SCL
I2C4_SDA: CN4.4(SDA) ; port I2C4_SDA
LCD_A0_RS: CN7.21(RS) ; port LCD_A0_RS
LCD_BL_CTRL: R55.2 U15.7(EN) ; port LCD_BL_CTRL
LCD_CTP_INT: CN4.2(INT) ; port LCD_CTP_INT
LCD_CTP_RST: CN4.7(RESET) ; port LCD_CTP_RST
LCD_D0: CN7.18(DB0)
LCD_D1: CN7.17(DB1)
LCD_D2: CN7.16(DB2)
LCD_D3: CN7.15(DB3)
LCD_D4: CN7.14(DB4)
LCD_D5: CN7.13(DB5)
LCD_D6: CN7.12(DB6)
LCD_D7: CN7.11(DB7)
LCD_D8: CN7.10(DB8)
LCD_D9: CN7.9(DB9)
LCD_D10: CN7.8(DB10)
LCD_D11: CN7.7(DB11)
LCD_D12: CN7.6(DB12)
LCD_D13: CN7.5(DB13)
LCD_D14: CN7.4(DB14)
LCD_D15: CN7.3(DB15)
LCD_NE1_CS: CN7.22(/CS) R44.1 ; port LCD_NE1_CS
LCD_NOE: CN7.19(/RD) ; port LCD_NOE
LCD_NWE: CN7.20(/WR) ; port LCD_NWE
LCD_PWR_ON: R101.1 R102.1 R103.2 ; port LCD_PWR_ON
LCD_RST: CN7.23(RESET) R41.2 ; port LCD_RST
LCD_TE: CN7.2(FMARK) ; port LCD_TE
LED_A: C49.2 CN7.28(LEDA) L2.2
LED_K: CN7.29(LEDK) R52.2 U15.4(FB)
NetC51_2: C51.2 C52.2 D1.2(K) L2.1 U15.6(Vo)
NetC53_2: C53.2 C54.1 L3.1 R49.2 U15.1(Vi)
NetC117_1: C117.1 Q2.1(G) R101.2
NetC118_1: C118.1 Q3.1(G) R102.2
NetCN7_24: CN7.24(IM) R43.1
NetD1_1: D1.1(A) L3.2 U15.8(SW)
NetR51_2: R51.2 U15.2(Rset)

Not connected (* = marked no-connect by the designer): U15 5(NC)*

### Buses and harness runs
bus LCD_D[0..15] = port LCD_D[0..15]

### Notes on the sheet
- PD3
- PD10
- PD8
- PE14
- PE12
- PE10
- PD9
- PE15
- PE13
- PE11
- PE9
- PE8
- PD1
- PD15
- PD4
- PF0
- PE7
- PD0
- PD14
- PD5
- PC7
- PH13
- LAYOUT: parts close to STLD40D and grounded in same area with Backlight GND as local ground plane.
- (near R103) PC6
- PG3
- PB9
- PB8
- PG7

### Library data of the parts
C3 C4 C117 C118 = MCD-00006: Capacitor, MLCC, 100nF, 16V, X7R, 10%, 0402, T=0.5mm; Manufacturer_Part_Number: CC0402KRX7R7BB104; Manufacturer: YAGEO; Alternate_Manufacturer_Part_Number: GCM155R71C104KA55D; Alternate_Manufacturer: MURATA; ECCN_US: EAR99; ECCN_EU: NEC; Provided_By: SUBCO
C48 C50 C54 = MCD-00006: Capacitor, MLCC, 100nF, 16V, X7R, 10%, 0402, T=0.5mm; Manufacturer_Part_Number: CC0402KRX7R7BB104; Manufacturer: YAGEO; Alternate_Manufacturer_Part_Number: GCM155R71C104KA55D; Alternate_Manufacturer: MURATA; Provided_By: SUBCO
C49 C52 = MCD-01099: Capacitor,100nF,50V,X7R,10%,0603; Manufacturer_Part_Number: CC0603KRX7R9BB104; Manufacturer: YAGEO; BMS_Part_Number: 9142278; Provided_By: SUBCO
C51 = MCD-00013: Capacitor, MLCC, 4.7uF, 50V, X7R, 10%, 1206, T=1,27mm; Manufacturer_Part_Number: 12065C475KAT2A; Manufacturer: AVX; ECCN_US: EAR99; ECCN_EU: NEC; Provided_By: SUBCO
C53 = MCD-00099: Capacitor, MLCC, 10uF, 10V, X5R, 10%, 0603, T=0,8mm; Manufacturer_Part_Number: GRM188R61A106KE69D; Manufacturer: MURATA; ECCN_US: EAR99; ECCN_EU: NEC; Provided_By: SUBCO
CN4 = MCD-00021: Socket FCC/FPC, 5x2, 0.4mm, VR, SMT, 0.98mm, Frida touch panel; Part_Type: Connector; Manufacturer_Part_Number: DF37NB-10DS-0.4V (5x); Manufacturer: HIROSE; Provided_By: SUBCO
CN7 = MCD-01798: Socket FCC/FPC, 29pins, 0.6mm, SMT, for FRIDA LCD (replacement of obsolete component MCD-00020 FH26-29S-0.3SHW); Part_Type: Connector; Manufacturer: HIROSE; Provided_By: SUBCO
D1 = MCD-00033: Low Drop power Schottky rectifier(1A, 40V, 0.4V); Part_Type: Diode; Manufacturer: STMICROELECTRONICS; BMS_Part_Number: 9151085; ECCN_US: EAR99; ECCN_EU: NEC; Provided_By: SUBCO with ST control
H1-H4 = MCD-00035: POSITION HOLE C6D3R5; Part_Type: Misc; Part_Preference: Recommended
HW4 = MCD-01797: TFT LCD 1.54inch 240RGB x 240 pixels + CTP; BMS_Part_Number: 8001061; Part_Type: Display; Part_Preference: Recommended; Manufacturer: SHENZEN FRIDA LCD CO.LTD; Manufacturer_Part_Number: FRD154B2902-D-CTQ
L2 = MCD-00047: SMD Chip ferrite bead, 600R@100MHz +/-25%, 350mA, 500mohm DC, 0603, T=0.8mm; Part_Type: Inductor; Manufacturer_Part_Number: FCM1608KF-601T03; Manufacturer: TAI-TECH; Provided_By: SUBCO
L3 = MCD-00048: FIXED IND 4.7UH 1A 180 MOHM 30% SMD; Manufacturer_Part_Number: LQH32PN4R7NN0L; Manufacturer: MURATA; Provided_By: SUBCO
Q2 Q3 = MCD-01494: MOSFET, P-Channel , Vds: -20V, Id: -2.4A, Vgs(th): -1.5V, Vgs(max): +/-8V, Rdson:100mohm@Vgs=-1.8V; Part_Type: IC; Manufacturer: ON SEMICONDUCTOR; Alternate_Manufacturer_Part_Number: FDN304PZ; ECCN_US: EAR99; ECCN_EU: NEC; Provided_By: SUBCO
R41 R44 R51 R55 R103 = MCD-00059: Resistor,100K,0402,1%,1/16W; Manufacturer_Part_Number: RC0402FR-07100KL; Manufacturer: YAGEO; Alternate_Manufacturer_Part_Number: RT0402FRE07100KL; ECCN_US: EAR99; ECCN_EU: NEC; Provided_By: SUBCO
R43 R49 R99 R100 = MCD-00052: Resistor,0R,0402,5%,1/16W; Manufacturer_Part_Number: RC0402JR-070RL; Manufacturer: YAGEO; ECCN_US: EAR99; ECCN_EU: NEC; Provided_By: SUBCO
R52 = MCD-00358: Resistor,10R,0402,1%,1/16W; Part_Preference: Recommended; Manufacturer: YAGEO; Manufacturer_Part_Number: RC0402FR-0710RL; Order_Code_RS: 618-5848
R101 R102 = MCD-00053: Resistor,10K,0402,1%,1/16W; Manufacturer_Part_Number: RC0402FR-0710KL; Manufacturer: YAGEO; BMS_Part_Number: 9131590; ECCN_US: EAR99; ECCN_EU: NEC; Provided_By: SUBCO
U15 = MCD-00082: White LED power supply for large display backlight, QFN8; Part_Type: IC; Manufacturer: STMICROELECTRONICS; BMS_Part_Number: 9176009; ECCN_US: EAR99; ECCN_EU: NEC; Provided_By: SUBCO with ST control

## Sheet Peripherals.SchDoc: Peripherals
size A4; Date: Not used; ApprovedBy: Not used; CheckedBy: Not used; Author: Not used; CompanyName: STMicroelectronics; DrawnBy: Not used; Engineer: Not used; Organization: Not used; Address1: Not used; Address2: Not used; Address3: Not used; Address4: Not used; DocumentNumber: 12; Revision: Not used; SheetNumber: 12; SheetTotal: 15
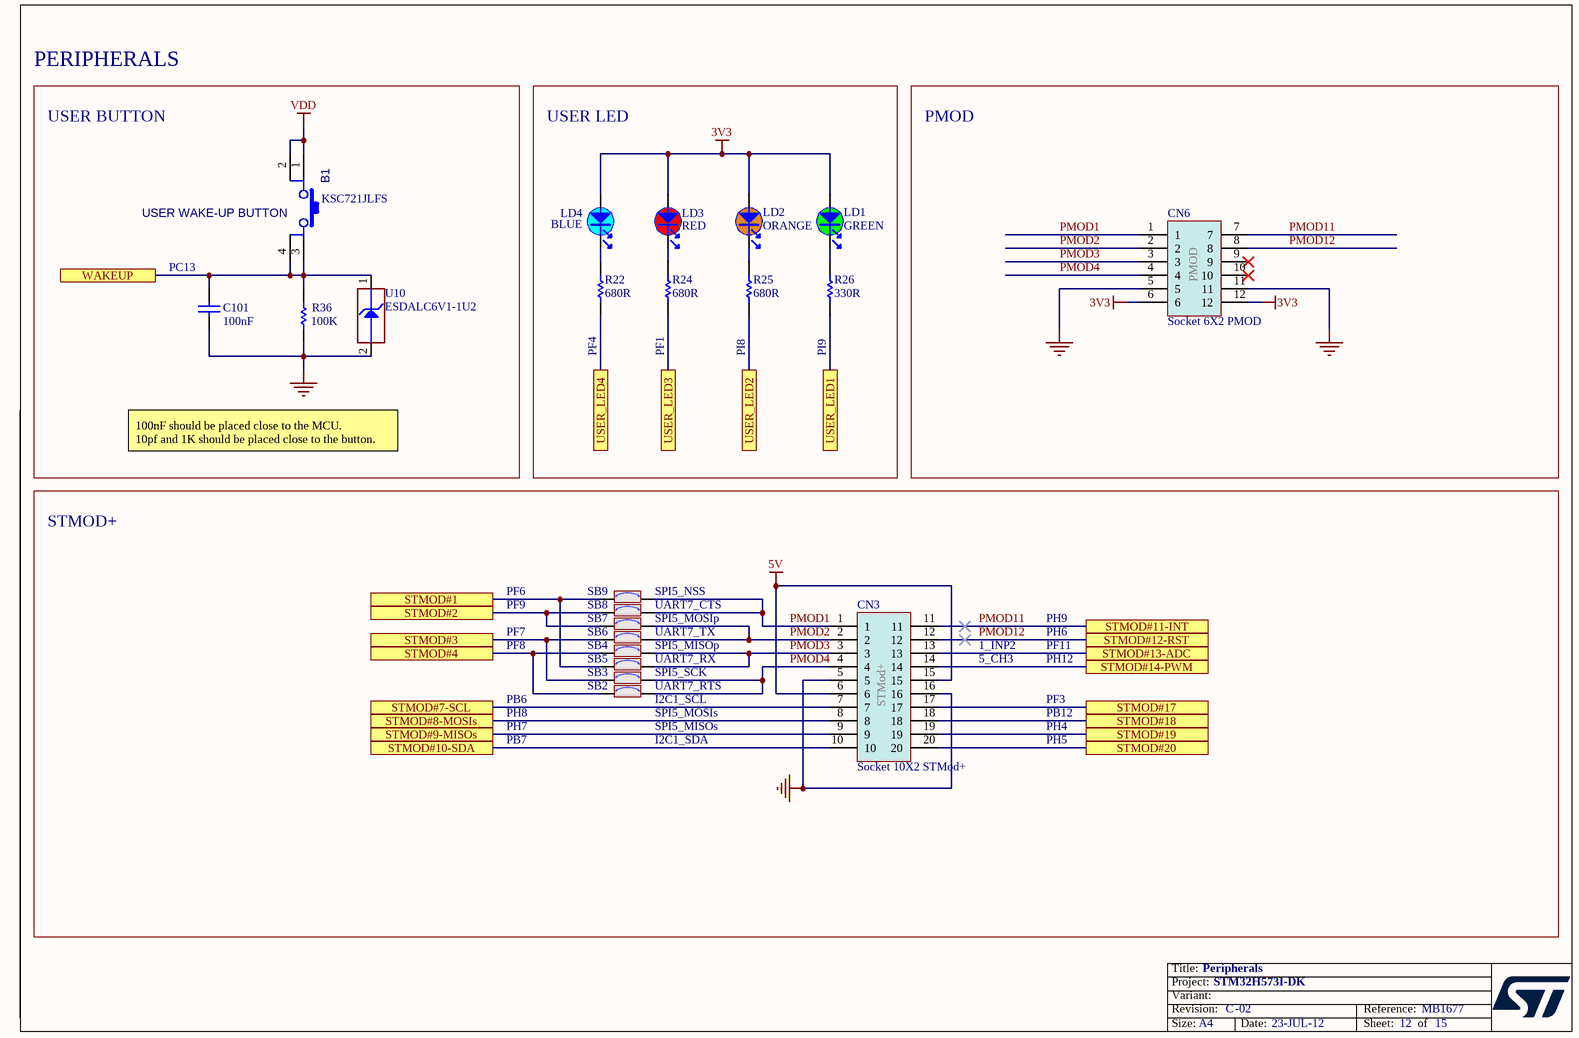
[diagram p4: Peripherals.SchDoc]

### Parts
B1  value KSC721JLFS  [SWI_C&K_KSC721JLFS_BLUE]  (hidden comment: SW_BLUE_KSC721JLFS)
C101  value 100nF  [C0402]  (hidden comment: Capacitor)
CN3  Socket 10X2 STMod+  [CON_SAMTEC_SQT-110-01-F-D-RA__STMOD+]
CN6  Socket 6X2 PMOD  [CON_SAMTEC_SSW-106-02-F-D-RA__PMOD]
LD1  value GREEN  [LED_0603_OSRAM_LG-Q396-PS-35_GREEN_1A2K_H0P4]  (hidden comment: LED_green)
LD2  value ORANGE  [LED_0603_OSRAM_LO-Q976-PS-25_ORANGE_1A2K_H0P8]  (hidden comment: LED_orange)
LD3  value RED  [LED_0603_VISHAY_VLMS1300-GS08_RED_1A2K_H0P8]  (hidden comment: LED_red)
LD4  value BLUE  [LED_0603_OSRAM_LB-Q39G-L2OO-35-1_BLUE_1A2K_H0P4]  (hidden comment: LED_blue)
R22  value 680R  [R0402]  (hidden comment: Resistor)
R24  value 680R  [R0402]  (hidden comment: Resistor)
R25  value 680R  [R0402]  (hidden comment: Resistor)
R26  value 330R  [R0402]  (hidden comment: Resistor)
R36  value 100K  [R0402]  (hidden comment: Resistor)
SB2  SB_ON  [SOLDER-BRIDGE_R0603-0R]  (value not drawn)
SB3  SB_ON  [SOLDER-BRIDGE_R0603-0R]  (value not drawn)
SB4  SB_ON  [SOLDER-BRIDGE_R0603-0R]  (value not drawn)
SB5  SB_ON  [SOLDER-BRIDGE_R0603-0R]  (value not drawn)
SB6  SB_ON  [SOLDER-BRIDGE_R0603-0R]  (value not drawn)
SB7  SB_ON  [SOLDER-BRIDGE_R0603-0R]  (value not drawn)
SB8  SB_ON  [SOLDER-BRIDGE_R0603-0R]  (value not drawn)
SB9  SB_ON  [SOLDER-BRIDGE_R0603-0R]  (value not drawn)
U10  value ESDALC6V1-1U2  [ESD_ST0201]  (hidden comment: ESD-TRANSIL)

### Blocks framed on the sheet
PERIPHERALS: B1 C101 R36 U10
USER LED: LD1-LD4 R22 R24-R26
PMOD: CN6
STMOD+: CN3 SB2-SB9

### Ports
STMOD#1, STMOD#2, STMOD#3, STMOD#4, STMOD#7-SCL, STMOD#8-MOSIs, STMOD#9-MISOs, STMOD#10-SDA, STMOD#11-INT, STMOD#12-RST, STMOD#13-ADC, STMOD#14-PWM, STMOD#17, STMOD#18, STMOD#19, STMOD#20, USER_LED1, USER_LED2, USER_LED3, USER_LED4, WAKEUP

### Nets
3V3: CN6.6 CN6.12 LD1.1 LD2.1 LD3.1 LD4.1
5V: CN3.6 CN3.15
GND: C101.1 CN3.5 CN3.16 CN6.5 CN6.11 R36.1 U10.2(GND)
VDD: B1.1 B1.2
PMOD1: CN3.1 CN6.1 SB8.2 SB9.2
PMOD2: CN3.2 CN6.2 SB6.2 SB7.2
PMOD3: CN3.3 CN6.3 SB4.2 SB5.2
PMOD4: CN3.4 CN6.4 SB2.2 SB3.2
PMOD11: CN3.11 CN6.7 ; port STMOD#11-INT
PMOD12: CN3.12 CN6.8 ; port STMOD#12-RST
STMOD#1: SB5.1 SB9.1 ; port STMOD#1
STMOD#2: SB7.1 SB8.1 ; port STMOD#2
STMOD#3: SB3.1 SB6.1 ; port STMOD#3
STMOD#4: SB2.1 SB4.1 ; port STMOD#4
STMOD#7-SCL: CN3.7 ; port STMOD#7-SCL
STMOD#8-MOSIs: CN3.8 ; port STMOD#8-MOSIs
STMOD#9-MISOs: CN3.9 ; port STMOD#9-MISOs
STMOD#10-SDA: CN3.10 ; port STMOD#10-SDA
STMOD#13-ADC: CN3.13 ; port STMOD#13-ADC
STMOD#14-PWM: CN3.14 ; port STMOD#14-PWM
STMOD#17: CN3.17 ; port STMOD#17
STMOD#18: CN3.18 ; port STMOD#18
STMOD#19: CN3.19 ; port STMOD#19
STMOD#20: CN3.20 ; port STMOD#20
USER_LED1: R26.1 ; port USER_LED1
USER_LED2: R25.1 ; port USER_LED2
USER_LED3: R24.1 ; port USER_LED3
USER_LED4: R22.1 ; port USER_LED4
WAKEUP: B1.3 B1.4 C101.2 R36.2 U10.1(IO1) ; port WAKEUP
NetLD1_2: LD1.2 R26.2
NetLD2_2: LD2.2 R25.2
NetLD3_2: LD3.2 R24.2
NetLD4_2: LD4.2 R22.2

Not connected (* = marked no-connect by the designer): CN6 9* 10*

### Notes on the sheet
- USER BUTTON
- (near B1) USER WAKE-UP BUTTON
- (near C101) PC13
- (near R22) PF4
- (near R24) PF1
- (near R25) PI8
- (near R26) PI9
- 100nF should be placed close to the MCU.
  10pf and 1K should be placed close to the button.
- PF6
- PF7
- PF8
- PF9
- SPI5_NSS
- UART7_CTS
- SPI5_MOSIp
- UART7_TX
- SPI5_MISOp
- 1_INP2
- PF11
- PH9
- PH6
- PB6
- PH8
- UART7_RX
- SPI5_SCK
- UART7_RTS
- SPI5_MOSIs
- I2C1_SCL
- 5_CH3
- PH12
- PF3
- PB12
- PB7
- PH7
- SPI5_MISOs
- I2C1_SDA
- PH5
- PH4

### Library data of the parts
B1 = MCD-01800: Switch HW BLUE High4.3mm 2.25 Newtons, BEND type; Part_Type: Misc; Part_Preference: Recommended; Manufacturer: C&K; Component_Country_Of_Origin: France; ShowFields: YES; ID: 3900
C101 = MCD-00006: as C48 on sheet LCD
CN3 = MCD-00309: Socket 10x2, 2.00mm, RA, TH, Height 6.35mm/2.29mm; Part_Preference: Recommended; Part_Type: Connector; Manufacturer: SAMTEC; Manufacturer_Part_Number: SQT-110-01-F-D-RA; Alternate_Manufacturer: JIUBABA;CONNECT; Alternate_Manufacturer_Part_Number: FH200020C-12300;CNT-F200-2*10-GD-635/2.3
CN6 = MCD-00308: Socket, 6x2, 2.54mm, TH, RA, Height 8.51mm/7.62mm; Part_Type: Connector; Manufacturer_Part_Number: SSW-106-02-F-D-RA; Manufacturer: SAMTEC; Provided_By: SUBCO
LD1 = MCD-00588: LED Green, 0603 SMD, Forward Voltage Typ=2V, Max=2.5V; Part_Preference: Recommended; Part_Type: Display; Manufacturer: OSRAM OPTO SEMICONDUCTORS; Manufacturer_Part_Number: LG Q396-PS-35; Alternate_Manufacturer: VISHAY SEMICONDUCTOR OPTO DIVISION; Alternate_Manufacturer_Part_Number: VLMTG1300-GS08
LD2 = MCD-00590: LED Orange, 0603 SMD, Forward Voltage Min=1.6V, Max=2.4V; Part_Preference: Recommended; Part_Type: Display; Manufacturer: OSRAM OPTO SEMICONDUCTORS; Manufacturer_Part_Number: LO Q976-PS-25; Alternate_Manufacturer: VISHAY SEMICONDUCTOR OPTO DIVISION; Alternate_Manufacturer_Part_Number: VLMO1300-GS08
LD3 = MCD-00587: LED Red, 0603 SMD, 2V Forward Voltage; Manufacturer_Part_Number: VLMS1300-GS08; Manufacturer: VISHAY; Alternate_Manufacturer_Part_Number: LS Q976-NR-1; Alternate_Manufacturer: OSRAM OPTO SEMICONDUCTORS; Part_Type: Display; Provided_By: SUBCO
LD4 = MCD-00585: LED Blue, 0603 SMD, Forward Voltage Min=2,8V, Max=3,8V; Manufacturer_Part_Number: LB Q39G-L2OO-35-1; Manufacturer: OSRAM OPTO SEMICONDUCTORS; Part_Type: Display; Alternate_Manufacturer_Part_Number: 19-217-BHC-ZL1M2RY-3T-V4; Alternate_Manufacturer: EVERLIGHT; Order_Code_RS: 9148643; Provided_By: SUBCO
R22 R24 R25 = MCD-00507: Resistor,680R,0402,1%,1/16W; Part_Preference: Recommended; Manufacturer: YAGEO; Manufacturer_Part_Number: RC0402FR-07680RL
R26 = MCD-00062: Resistor,330R,0402,1%,1/16W; Manufacturer_Part_Number: RC0402FR-07330RL; Manufacturer: YAGEO; Provided_By: SUBCO
R36 = MCD-00059: as R77 on sheet Audio_Codec
SB2-SB9 = MCD-00071: as SB1 on sheet Audio_Codec
U10 = MCD-00170: ESD protection 6V1; Part_Type: Diode; Manufacturer: STMICROELECTRONICS; BMS_Part_Number: 9151132; Provided_By: SUBCO with ST control

## Sheet Arduino.SchDoc: Arduino
size A4; Date: Not used; ApprovedBy: Not used; CheckedBy: Not used; Author: Not used; CompanyName: STMicroelectronics; DrawnBy: Not used; Engineer: Not used; Organization: Not used; Address1: Not used; Address2: Not used; Address3: Not used; Address4: Not used; DocumentNumber: 11; Revision: Not used; SheetNumber: 11; SheetTotal: 15
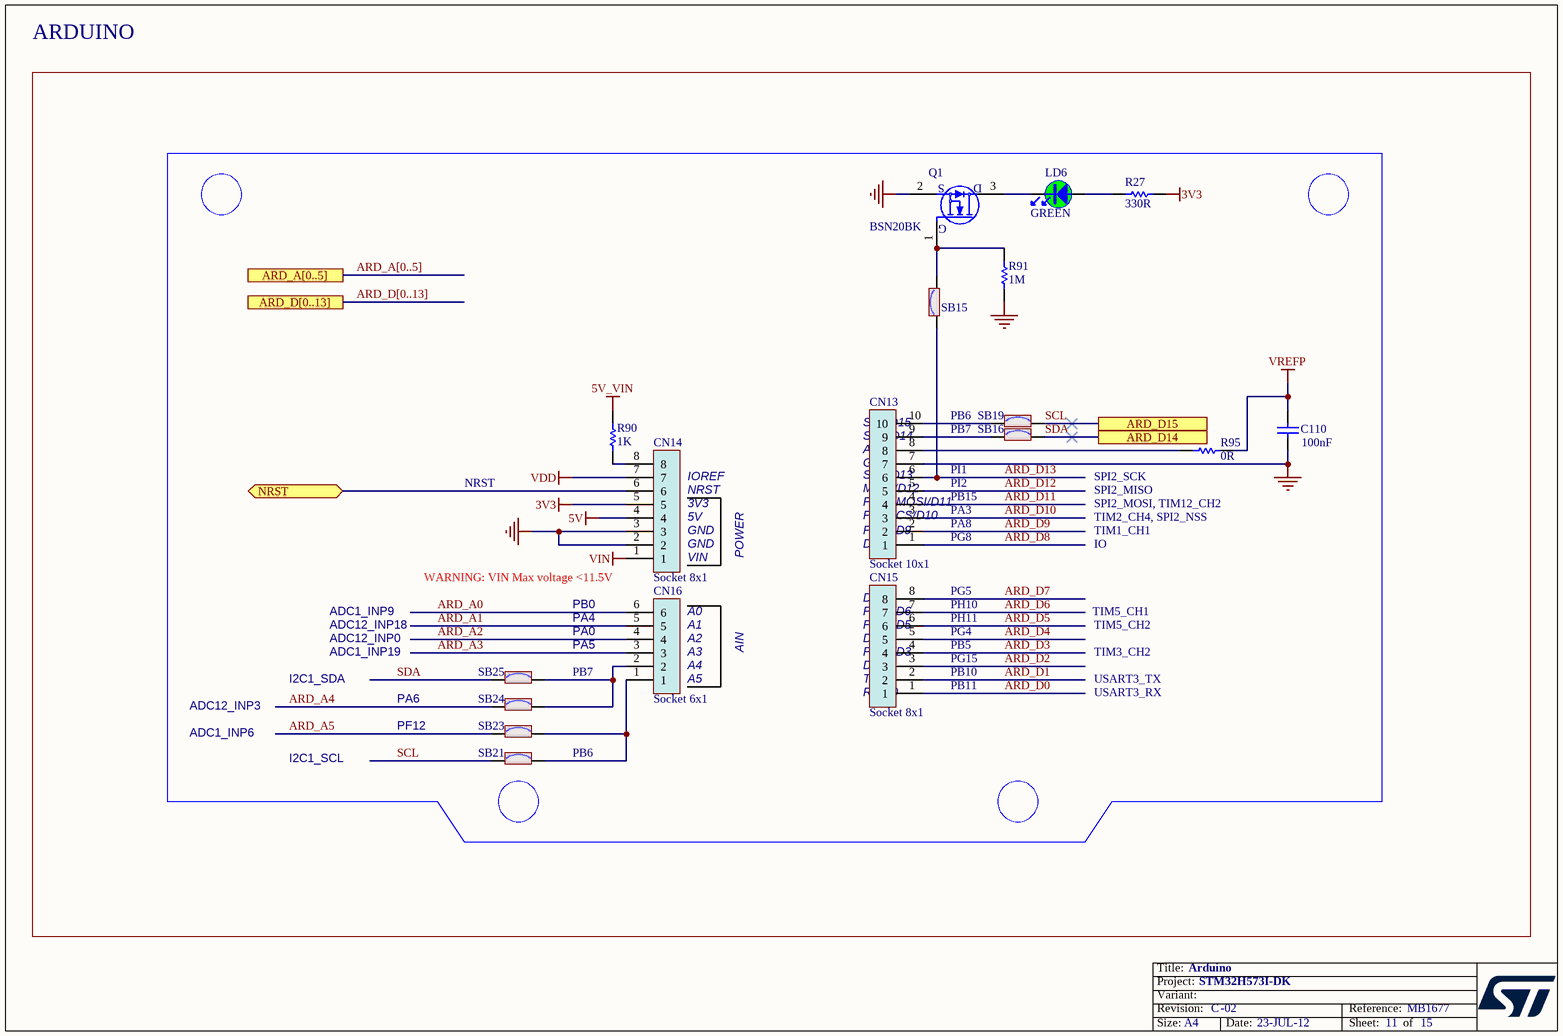
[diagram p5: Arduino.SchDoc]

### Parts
C110  value 100nF  [C0402]  (hidden comment: Capacitor)
CN13  Socket 10x1  [CON_SAMTEC_SSM-110-L-SV]
CN14  Socket 8x1  [CON_SAMTEC_SSM-108-L-SV]
CN15  Socket 8x1  [CON_SAMTEC_SSM-108-L-SV]
CN16  Socket 6x1  [CON_SAMTEC_SSM-106-L-SV]
LD6  value GREEN  [LED_0603_OSRAM_LG-Q396-PS-35_GREEN_1A2K_H0P4]  (hidden comment: LED_green)
Q1  value BSN20BK  [MOS_SOT23]  (hidden comment: BSN20)
R27  value 330R  [R0402]  (hidden comment: Resistor)
R90  value 1K  [R0402]  (hidden comment: Resistor)
R91  value 1M  [R0402]  (hidden comment: Resistor)
R95  value 0R  [R0402]  (hidden comment: Resistor)
SB15  SB_ON  [SOLDER-BRIDGE_R0603-0R]  (value not drawn)
SB16  SB_ON  [SOLDER-BRIDGE_R0603-0R]  (value not drawn)
SB19  SB_ON  [SOLDER-BRIDGE_R0603-0R]  (value not drawn)
SB21  SB_ON  [SOLDER-BRIDGE_R0603-0R]  (value not drawn)
SB23  SB_ON  [SOLDER-BRIDGE_R0603-0R]  (value not drawn)
SB24  SB_ON  [SOLDER-BRIDGE_R0603-0R]  (value not drawn)
SB25  SB_ON  [SOLDER-BRIDGE_R0603-0R]  (value not drawn)

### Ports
ARD_A[0..5], ARD_D14, ARD_D15, ARD_D[0..13], NRST (bidir)

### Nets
3V3: CN14.5 R27.2
5V: CN14.4
5V_VIN: R90.2
GND: C110.2 CN13.7 CN14.2 CN14.3 Q1.2(S) R91.1
VDD: CN14.7
VIN: CN14.1
VREFP: C110.1 R95.2
ARD_A0: CN16.6
ARD_A1: CN16.5
ARD_A2: CN16.4
ARD_A3: CN16.3
ARD_A4: SB24.1
ARD_A5: SB23.1
ARD_D0: CN15.1
ARD_D1: CN15.2
ARD_D2: CN15.3
ARD_D3: CN15.4
ARD_D4: CN15.5
ARD_D5: CN15.6
ARD_D6: CN15.7
ARD_D7: CN15.8
ARD_D8: CN13.1
ARD_D9: CN13.2
ARD_D10: CN13.3
ARD_D11: CN13.4
ARD_D12: CN13.5
ARD_D13: CN13.6 SB15.1
NRST: CN14.6 ; port NRST
SCL: SB19.2 SB21.1 ; port ARD_D15
SDA: SB16.2 SB25.1 ; port ARD_D14
NetCN13_8: CN13.8 R95.1
NetCN13_9: CN13.9 SB16.1
NetCN13_10: CN13.10 SB19.1
NetCN14_8: CN14.8 R90.1
NetCN16_1: CN16.1 SB21.2 SB23.2
NetCN16_2: CN16.2 SB24.2 SB25.2
NetLD6_1: LD6.1 R27.1
NetLD6_2: LD6.2 Q1.3(D)
NetQ1_1: Q1.1(G) R91.2 SB15.2

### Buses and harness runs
bus ARD_A[0..5] = port ARD_A[0..5]
bus ARD_D[0..13] = port ARD_D[0..13]

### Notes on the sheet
- ARDUINO
- (near CN13) SDA/D14
- (near CN13) SCL/D15
- PB6
- PB7
- NRST
- (near CN14) IOREF
- (near CN14) NRST
- (near CN14) 3V3
- (near CN14) 5V
- (near CN13) PWM/CS/D10
- (near CN13) SCK/D13
- (near CN13) MISO/D12
- (near CN13) PWM/MOSI/D11
- (near CN13) AVDD
- (near CN13) GND
- PA3
- PI1
- PI2
- PB15
- TIM2_CH4, SPI2_NSS
- (near R95) SPI2_MOSI, TIM12_CH2
- SPI2_SCK
- SPI2_MISO
- WARNING: VIN Max voltage <11.5V
- (near CN14) GND
- (near CN14) VIN
- POWER
- (near CN13) D8
- (near CN13) PWM/D9
- PG8
- PA8
- TIM1_CH1
- IO
- ADC12_INP0
- ADC1_INP19
- ADC1_INP9
- ADC12_INP18
- PA5
- PA0
- PA4
- PB0
- (near CN16) A0
- (near CN16) A1
- (near CN16) A2
- (near CN16) A3
- AIN
- (near CN15) D4
- (near CN15) PWM/D3
- (near CN15) PWM/D5
- (near CN15) PWM/D6
- (near CN15) D7
- PB5
- PH10
- PG4
- PG5
- PH11
- TIM5_CH1
- TIM5_CH2
- TIM3_CH2
- ADC12_INP3
- I2C1_SDA
- PA6
- (near CN16) A4
- (near CN16) A5
- (near CN15) RX/D0
- (near CN15) TX/D1
- (near CN15) D2
- PG15
- PB11
- PB10
- USART3_TX
- USART3_RX
- ADC1_INP6
- I2C1_SCL
- PF12

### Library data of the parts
C110 = MCD-00006: as C48 on sheet LCD
CN13 = MCD-02342: Socket, 10x1, 2.54mm, VR, SMD, T=7.37mm; Part_Type: Connector; Part_Preference: Recommended; Manufacturer: SAMTEC; Manufacturer_Part_Number: SSM-110-L-SV; Order_Code_RS: 765-5420; Component_Country_Of_Origin: China, Costa Rica, Malaysia, United States, Vietnam; ShowFields: YES; ID: 4448
CN14 CN15 = MCD-02345: Socket, 8x1, 2.54mm, VR, SMD, T=7.37mm; Part_Type: Connector; Part_Preference: Recommended; Manufacturer: SAMTEC; Manufacturer_Part_Number: SSM-108-L-SV; Order_Code_RS: 765-5411; Component_Country_Of_Origin: China, Costa Rica, Malaysia, United States, Vietnam; ShowFields: YES; ID: 4451
CN16 = MCD-02346: Socket, 6x1, 2.54mm, VR, SMD, T=7.37mm; Part_Type: Connector; Part_Preference: Recommended; Manufacturer: SAMTEC; Manufacturer_Part_Number: SSM-106-L-SV; Order_Code_RS: 765-5408; Component_Country_Of_Origin: China, Costa Rica, Malaysia, United States, Vietnam; ShowFields: YES; ID: 4452
LD6 = MCD-00588: LED Green, 0603 SMD, Forward Voltage Typ=2V, Max=2.5V; Part_Type: Display; Manufacturer_Part_Number: LG Q396-PS-35; Manufacturer: OSRAM OPTO SEMICONDUCTORS; Alternate_Manufacturer_Part_Number: VLMTG1300-GS08; Alternate_Manufacturer: VISHAY SEMICONDUCTOR OPTO DIVISION; Provided_By: SUBCO
Q1 = MCD-01969: Transistor, N-channel enhancement mode field-effect transistor; Part_Preference: Recommended; Manufacturer: NEXPERIA; Order_Code_RS: 136-4845
R27 = MCD-00062: as R26 on sheet Peripherals
R90 = MCD-00061: Resistor,1K,0402,1%,1/16W; Manufacturer_Part_Number: RC0402FR-071KL; Manufacturer: YAGEO; Provided_By: SUBCO
R91 = MCD-00182: Resistor,1M,0402,1%,1/16W; Manufacturer_Part_Number: RC0402FR-071ML; Manufacturer: YAGEO; Provided_By: SUBCO
R95 = MCD-00052: Resistor,0R,0402,5%,1/16W; Manufacturer_Part_Number: RC0402JR-070RL; Manufacturer: YAGEO; Provided_By: SUBCO
SB15 SB16 SB19 SB21 SB23-SB25 = MCD-00071: as SB1 on sheet Audio_Codec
